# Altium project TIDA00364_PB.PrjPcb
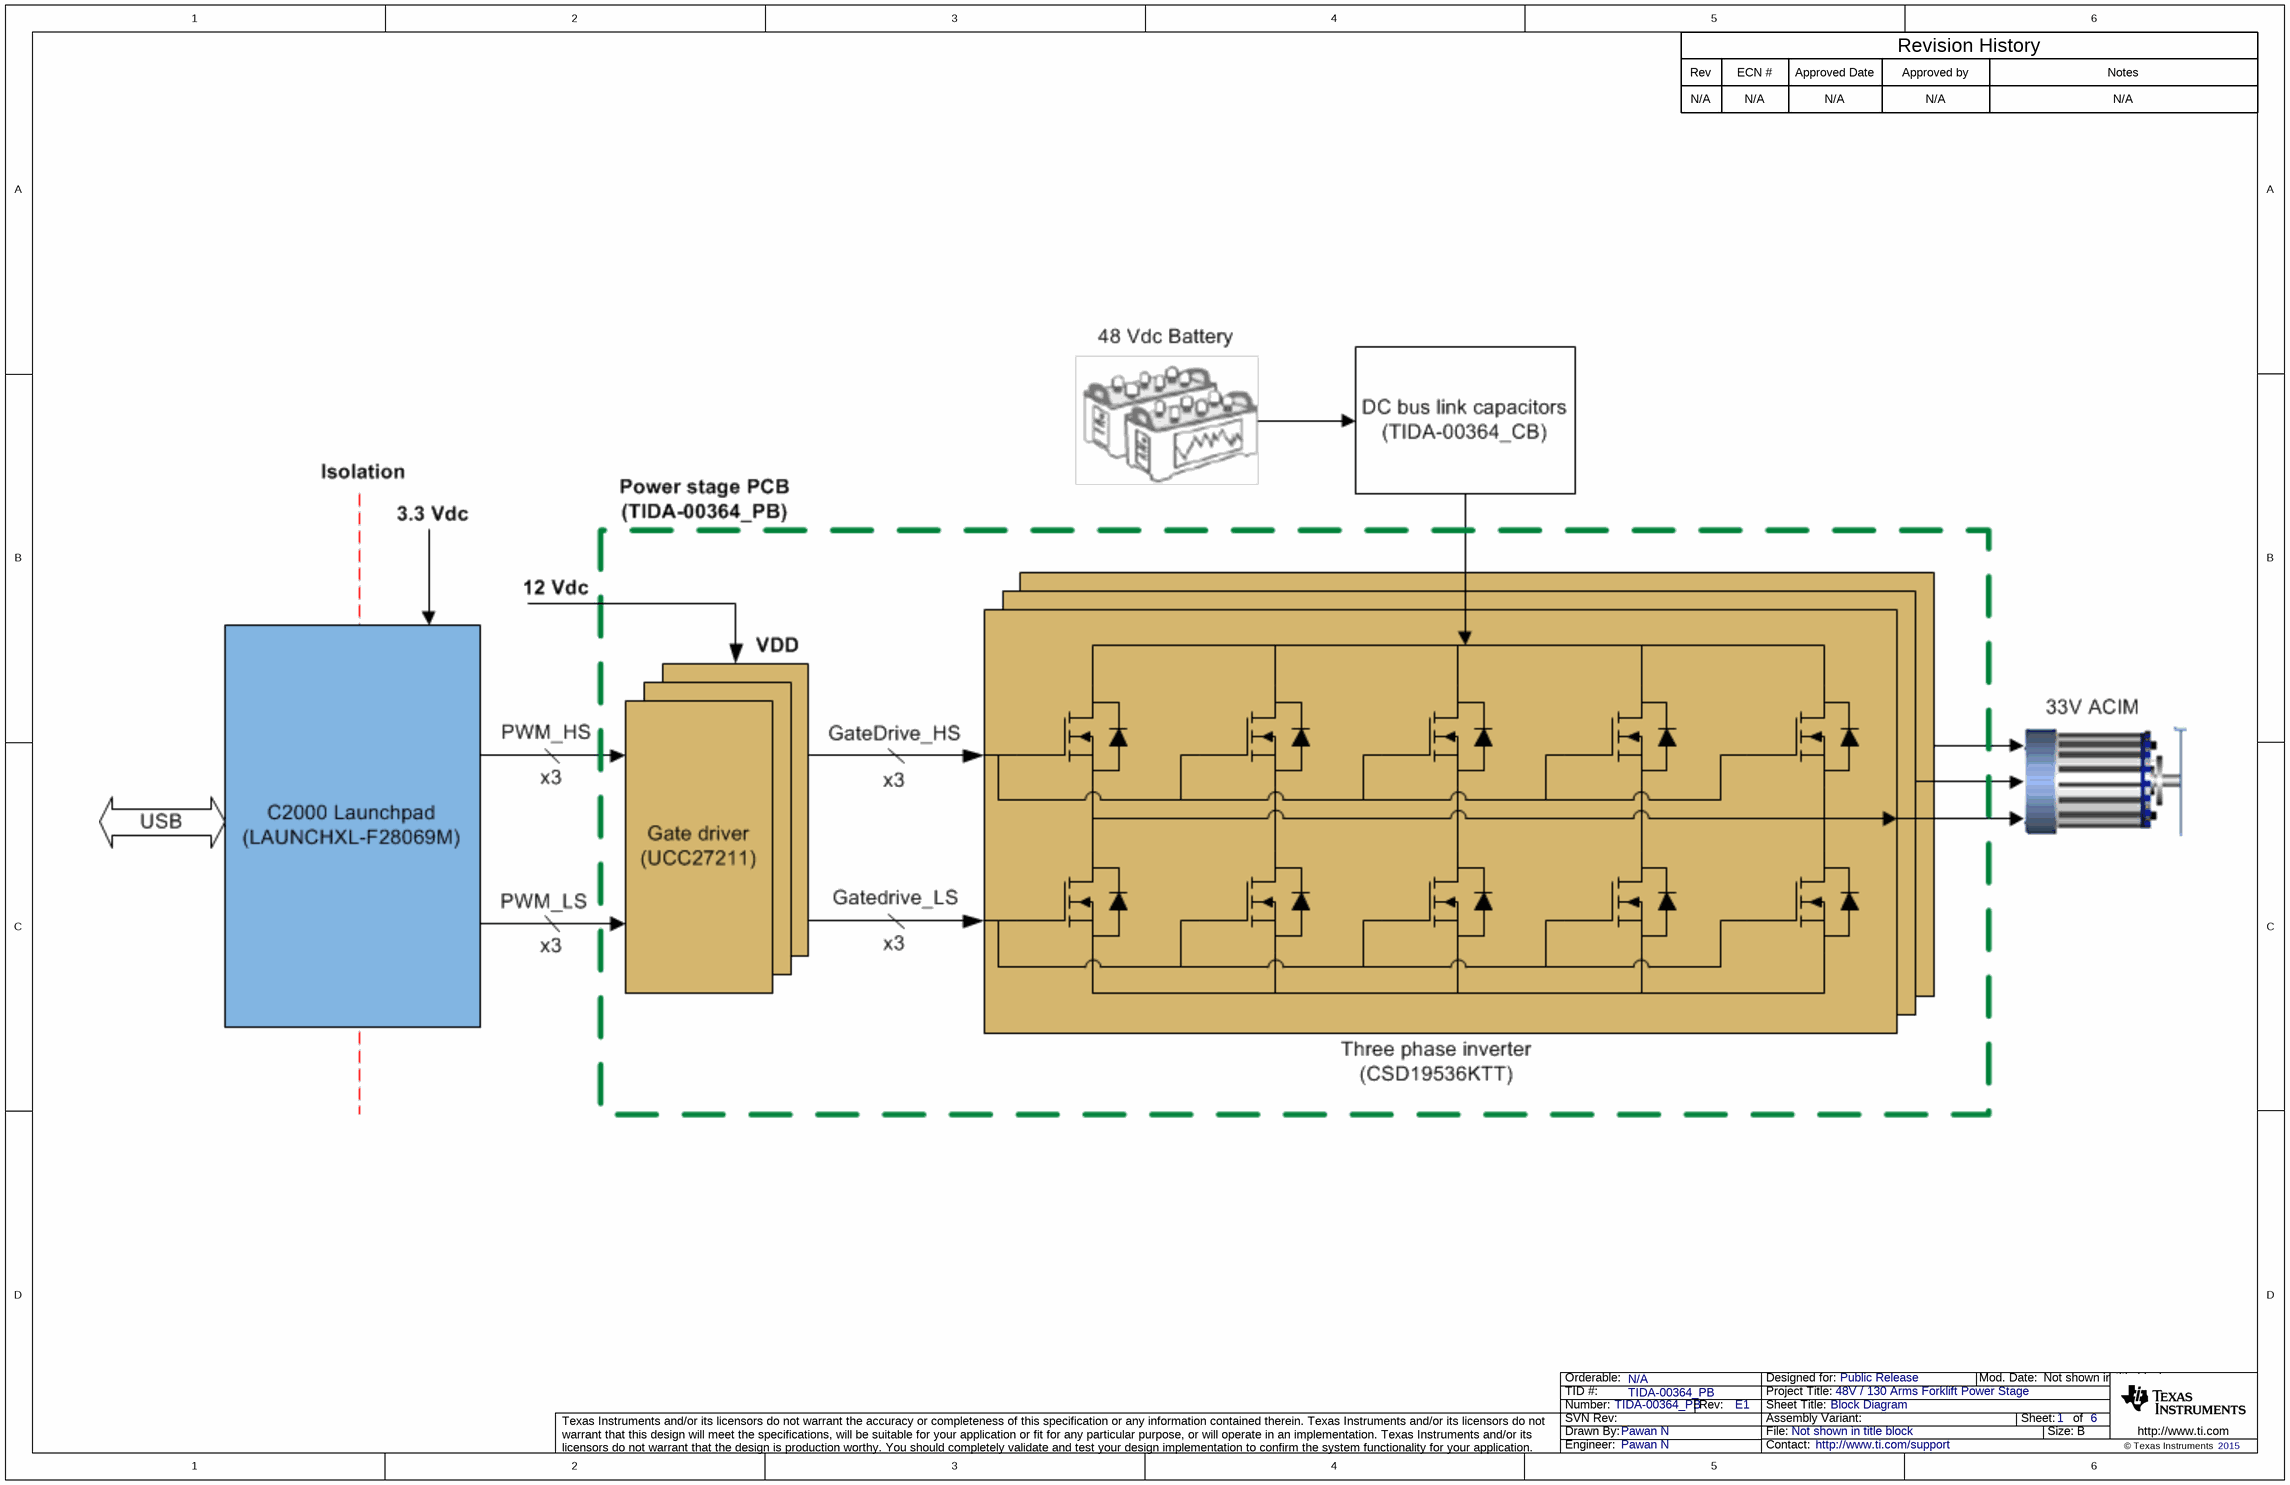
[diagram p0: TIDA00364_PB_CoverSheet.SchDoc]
CopyrightYear: 2015; EVM_Orderable: N/A; PCB_Layout: Avinash; PCB_Rev: E1; PRJ_Customer: Public Release; PRJ_Engineer: Pawan N; PRJ_Number: TIDA-00364_PB; PRJ_Title: 48V / 130 Arms Forklift Power Stage; SCH_Rev: E1; TechSupport: http://www.ti.com/support; TID: TIDA-00364_PB
6 sheets, 245 parts. Net scope: global (net labels, ports and power ports of the same name join across sheets).
Board file: TIDA00364_PB.PcbDoc
Sheets:
  TIDA00364_PB_CoverSheet.SchDoc
  TIDA00364_PB_GateDriver.SchDoc
  TIDA00364_PB_PhaseU.SchDoc
  TIDA00364_PB_PhaseV.SchDoc
  TIDA00364_PB_PhaseW.SchDoc
  TIDA00364_PB_Hardware.SchDoc

## Sheet TIDA00364_PB_CoverSheet.SchDoc: Block Diagram
size 431 x 279 mm; Date: Not shown in title block; ApprovedBy: Not shown in title block; CheckedBy: Not shown in title block; Author: Not shown in title block; CompanyName: Not shown in title block; DrawnBy: Pawan N; Engineer: Not shown in title block; Organization: Not shown in title block; Address1: Not shown in title block; Address2: Not shown in title block; Address3: Not shown in title block; Address4: Not shown in title block; DocumentNumber: 1; Revision: Use project parameter SCH_Rev; SheetNumber: 1; SheetTotal: 6; PageSetup: Record=PageOptions¦CenterHorizontal=True¦CenterVertical=True¦PrintScale=1.00¦XCorrection=1.00¦YCorrection=1.00¦PrintKind=0¦BorderSize=5000000¦LeftOffset=0¦BottomOffset=0¦Orientation=2¦PaperLength=1000¦PaperWidth=1000¦Scale=100¦PaperSource=15¦PrintQuality=600¦MediaType=1¦DitherType=10¦PaperKind=Letter¦PrintScaleMode=1

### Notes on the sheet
- Rev
- N/A
- ECN #
- Approved Date
- Approved by
- Revision History
- Notes

## Sheet TIDA00364_PB_GateDriver.SchDoc: Gate drive
size 431 x 279 mm; Date: Not shown in title block; ApprovedBy: Not shown in title block; CheckedBy: Not shown in title block; Author: Not shown in title block; CompanyName: Not shown in title block; DrawnBy: Pawan N; Engineer: Not shown in title block; Organization: Not shown in title block; Address1: Not shown in title block; Address2: Not shown in title block; Address3: Not shown in title block; Address4: Not shown in title block; DocumentNumber: 2; Revision: Use project parameter SCH_Rev; SheetNumber: 2; SheetTotal: 6; PageSetup: Record=PageOptions¦CenterHorizontal=True¦CenterVertical=True¦PrintScale=1.00¦XCorrection=1.00¦YCorrection=1.00¦PrintKind=0¦BorderSize=5000000¦LeftOffset=0¦BottomOffset=0¦Orientation=2¦PaperLength=1000¦PaperWidth=1000¦Scale=100¦PaperSource=15¦PrintQuality=600¦MediaType=1¦DitherType=10¦PaperKind=Letter¦PrintScaleMode=1
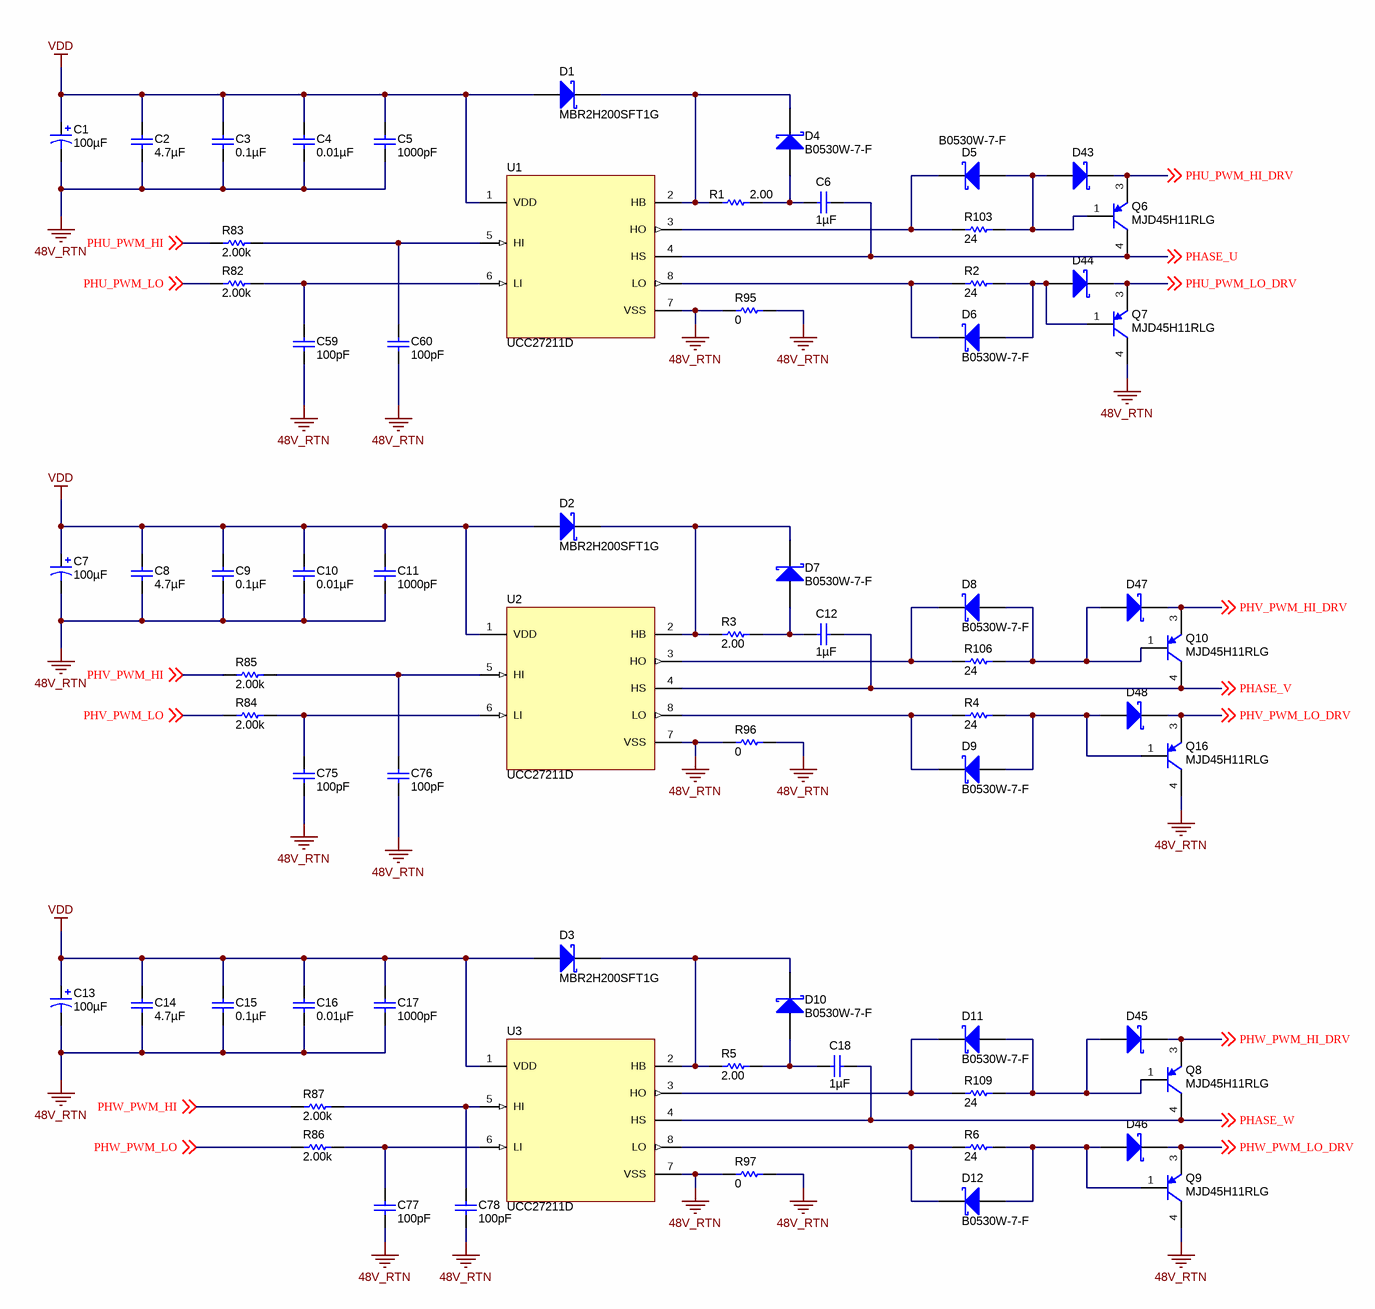
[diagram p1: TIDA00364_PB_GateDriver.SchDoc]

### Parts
C1  ValueDisplayed: 100µF  [SM_RADIAL_D8]  (hidden comment: EEE-FK1V101XP)
C2  ValueDisplayed: 4.7µF  [1206]  (hidden comment: GRM31CR71E475KA88L)
C3  ValueDisplayed: 0.1µF  [0603]  (hidden comment: C1608X7R1E104K)
C4  ValueDisplayed: 0.01µF  [0603]  (hidden comment: C1608X7R1H103K)
C5  ValueDisplayed: 1000pF  [0603]  (hidden comment: GRM188R71H102KA01D)
C6  ValueDisplayed: 1µF  [1206]  (hidden comment: C3216X7R1H105K160AB)
C7  ValueDisplayed: 100µF  [SM_RADIAL_D8]  (hidden comment: EEE-FK1V101XP)
C8  ValueDisplayed: 4.7µF  [1206]  (hidden comment: GRM31CR71E475KA88L)
C9  ValueDisplayed: 0.1µF  [0603]  (hidden comment: C1608X7R1E104K)
C10  ValueDisplayed: 0.01µF  [0603]  (hidden comment: C1608X7R1H103K)
C11  ValueDisplayed: 1000pF  [0603]  (hidden comment: GRM188R71H102KA01D)
C12  ValueDisplayed: 1µF  [1206]  (hidden comment: C3216X7R1H105K160AB)
C13  ValueDisplayed: 100µF  [SM_RADIAL_D8]  (hidden comment: EEE-FK1V101XP)
C14  ValueDisplayed: 4.7µF  [1206]  (hidden comment: GRM31CR71E475KA88L)
C15  ValueDisplayed: 0.1µF  [0603]  (hidden comment: C1608X7R1E104K)
C16  ValueDisplayed: 0.01µF  [0603]  (hidden comment: C1608X7R1H103K)
C17  ValueDisplayed: 1000pF  [0603]  (hidden comment: GRM188R71H102KA01D)
C18  ValueDisplayed: 1µF  [1206]  (hidden comment: C3216X7R1H105K160AB)
C59  ValueDisplayed: 100pF  [0402]  (hidden comment: C0402C101J3GACTU)
C60  ValueDisplayed: 100pF  [0402]  (hidden comment: C0402C101J3GACTU)
C75  ValueDisplayed: 100pF  [0402]  (hidden comment: C0402C101J3GACTU)
C76  ValueDisplayed: 100pF  [0402]  (hidden comment: C0402C101J3GACTU)
C77  ValueDisplayed: 100pF  [0402]  (hidden comment: C0402C101J3GACTU)
C78  ValueDisplayed: 100pF  [0402]  (hidden comment: C0402C101J3GACTU)
D1  MBR2H200SFT1G  [SOD-123FL]
D2  MBR2H200SFT1G  [SOD-123FL]
D3  MBR2H200SFT1G  [SOD-123FL]
D4  B0530W-7-F  [SOD-123]
D5  B0530W-7-F  [SOD-123]
D6  B0530W-7-F  [SOD-123]
D7  B0530W-7-F  [SOD-123]
D8  B0530W-7-F  [SOD-123]
D9  B0530W-7-F  [SOD-123]
D10  B0530W-7-F  [SOD-123]
D11  B0530W-7-F  [SOD-123]
D12  B0530W-7-F  [SOD-123]
D43  B0530W-7-F  [SOD-123]  (value not drawn)
D44  B0530W-7-F  [SOD-123]  (value not drawn)
D45  B0530W-7-F  [SOD-123]  (value not drawn)
D46  B0530W-7-F  [SOD-123]  (value not drawn)
D47  B0530W-7-F  [SOD-123]  (value not drawn)
D48  B0530W-7-F  [SOD-123]  (value not drawn)
Q6  MJD45H11RLG  [DPAK]
Q7  MJD45H11RLG  [DPAK]
Q8  MJD45H11RLG  [DPAK]
Q9  MJD45H11RLG  [DPAK]
Q10  MJD45H11RLG  [DPAK]
Q16  MJD45H11RLG  [DPAK]
R1  ValueDisplayed: 2.00  [1206]  (hidden comment: CRCW12062R00FKEA)
R2  ValueDisplayed: 24  [1206]  (hidden comment: CRCW120624R0JNEA)
R3  ValueDisplayed: 2.00  [1206]  (hidden comment: CRCW12062R00FKEA)
R4  ValueDisplayed: 24  [1206]  (hidden comment: CRCW120624R0JNEA)
R5  ValueDisplayed: 2.00  [1206]  (hidden comment: CRCW12062R00FKEA)
R6  ValueDisplayed: 24  [1206]  (hidden comment: CRCW120624R0JNEA)
R82  ValueDisplayed: 2.00k  [0402]  (hidden comment: CRCW04022K00FKED)
R83  ValueDisplayed: 2.00k  [0402]  (hidden comment: CRCW04022K00FKED)
R84  ValueDisplayed: 2.00k  [0402]  (hidden comment: CRCW04022K00FKED)
R85  ValueDisplayed: 2.00k  [0402]  (hidden comment: CRCW04022K00FKED)
R86  ValueDisplayed: 2.00k  [0402]  (hidden comment: CRCW04022K00FKED)
R87  ValueDisplayed: 2.00k  [0402]  (hidden comment: CRCW04022K00FKED)
R95  ValueDisplayed: 0  [1206]  (hidden comment: CRCW12060000Z0EA)
R96  ValueDisplayed: 0  [1206]  (hidden comment: CRCW12060000Z0EA)
R97  ValueDisplayed: 0  [1206]  (hidden comment: CRCW12060000Z0EA)
R103  ValueDisplayed: 24  [1206]  (hidden comment: CRCW120624R0JNEA)
R106  ValueDisplayed: 24  [1206]  (hidden comment: CRCW120624R0JNEA)
R109  ValueDisplayed: 24  [1206]  (hidden comment: CRCW120624R0JNEA)
U1  UCC27211D  [D0008A_N]
U2  UCC27211D  [D0008A_N]
U3  UCC27211D  [D0008A_N]

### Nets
48V_RTN: C1.2(-) C2.2 C3.1 C4.2 C5.2 C7.2(-) C8.2 C9.1 C10.2 C11.2 C13.2(-) C14.2 C15.1 C16.2 C17.2 C59.2 C60.2 C75.2 C76.2 C77.2 C78.2 Q7.4(C) Q9.4(C) Q16.4(C) R95.1 R95.2 R96.1 R96.2 R97.1 R97.2 U1.7(VSS) U2.7(VSS) U3.7(VSS)
VDD: C1.1(+) C2.1 C3.2 C4.1 C5.1 C7.1(+) C8.1 C9.2 C10.1 C11.1 C13.1(+) C14.1 C15.2 C16.1 C17.1 D1.2(A) D2.2(A) D3.2(A) U1.1(VDD) U2.1(VDD) U3.1(VDD)
PHASE_U: C6.2 Q6.4(C) U1.4(HS) ; off-sheet PHASE_U
PHASE_V: C12.2 Q10.4(C) U2.4(HS) ; off-sheet PHASE_V
PHASE_W: C18.2 Q8.4(C) U3.4(HS) ; off-sheet PHASE_W
PHU_PWM_HI: R83.2 ; off-sheet PHU_PWM_HI
PHU_PWM_HI_DRV: D43.1(K) Q6.3(E) ; off-sheet PHU_PWM_HI_DRV
PHU_PWM_LO: R82.2 ; off-sheet PHU_PWM_LO
PHU_PWM_LO_DRV: D44.1(K) Q7.3(E) ; off-sheet PHU_PWM_LO_DRV
PHV_PWM_HI: R85.2 ; off-sheet PHV_PWM_HI
PHV_PWM_HI_DRV: D47.1(K) Q10.3(E) ; off-sheet PHV_PWM_HI_DRV
PHV_PWM_LO: R84.2 ; off-sheet PHV_PWM_LO
PHV_PWM_LO_DRV: D48.1(K) Q16.3(E) ; off-sheet PHV_PWM_LO_DRV
PHW_PWM_HI: R87.2 ; off-sheet PHW_PWM_HI
PHW_PWM_HI_DRV: D45.1(K) Q8.3(E) ; off-sheet PHW_PWM_HI_DRV
PHW_PWM_LO: R86.2 ; off-sheet PHW_PWM_LO
PHW_PWM_LO_DRV: D46.1(K) Q9.3(E) ; off-sheet PHW_PWM_LO_DRV
NetC6_1: C6.1 D4.2(A) R1.2
NetC12_1: C12.1 D7.2(A) R3.2
NetC18_1: C18.1 D10.2(A) R5.2
NetC59_1: C59.1 R82.1 U1.6(LI)
NetC60_1: C60.1 R83.1 U1.5(HI)
NetC75_1: C75.1 R84.1 U2.6(LI)
NetC76_1: C76.1 R85.1 U2.5(HI)
NetC77_1: C77.1 R86.1 U3.6(LI)
NetC78_1: C78.1 R87.1 U3.5(HI)
NetD1_1: D1.1(K) D4.1(K) R1.1 U1.2(HB)
NetD2_1: D2.1(K) D7.1(K) R3.1 U2.2(HB)
NetD3_1: D3.1(K) D10.1(K) R5.1 U3.2(HB)
NetD5_1: D5.1(K) R103.1 U1.3(HO)
NetD5_2: D5.2(A) D43.2(A) Q6.1(B) R103.2
NetD6_1: D6.1(K) R2.1 U1.8(LO)
NetD6_2: D6.2(A) D44.2(A) Q7.1(B) R2.2
NetD8_1: D8.1(K) R106.1 U2.3(HO)
NetD8_2: D8.2(A) D47.2(A) Q10.1(B) R106.2
NetD9_1: D9.1(K) R4.1 U2.8(LO)
NetD9_2: D9.2(A) D48.2(A) Q16.1(B) R4.2
NetD11_1: D11.1(K) R109.1 U3.3(HO)
NetD11_2: D11.2(A) D45.2(A) Q8.1(B) R109.2
NetD12_1: D12.1(K) R6.1 U3.8(LO)
NetD12_2: D12.2(A) D46.2(A) Q9.1(B) R6.2

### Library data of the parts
C1 C7 C13 = EEE-FK1V101XP: CAP, AL, 100 µF, 35 V, +/- 20%, 0.34 ohm, SMD; Manufacturer: Panasonic; Polarized: Y; CompType: Capacitor; Value: 100uF; U/M: EA; Cap_F: 0.0001; Tolerance_%: 20; VDC_V: 35; Value2: 35V; ESR_ohm: 0.34; IRMS_A: 0.28; TaMin_C: -55; TaMax_C: 105; Cap_Case: D8; AEC Category: Q200
C2 C8 C14 = GRM31CR71E475KA88L: CAP, CERM, 4.7 µF, 25 V, +/- 10%, X7R, 1206; Manufacturer: MuRata; Polarized: N; CompType: Capacitor; Value: 4.7uF; U/M: EA; Cap_F: 0.0000047; Tolerance_%: 10; Value1: Unknown; VDC_V: 25; Value2: 25V; TaMin_C: -55; TaMax_C: 125; AEC Category: Q200
C3 C9 C15 = C1608X7R1E104K: CAP, CERM, 0.1 µF, 25 V, +/- 10%, X7R, 0603; Manufacturer: TDK; Polarized: N; CompType: Capacitor; Value: 0.1uF; U/M: EA; Cap_F: 0.0000001; Tolerance_%: 10; ESR_ohm: 0.017; Value1: 0.017 ohm; VDC_V: 25; Value2: 25V; TaMin_C: -55; TaMax_C: 125; AEC Category: Q200
C4 C10 C16 = C1608X7R1H103K: CAP, CERM, 0.01 µF, 50 V, +/- 10%, X7R, 0603; Manufacturer: TDK; Polarized: N; CompType: Capacitor; Value: 0.01uF; U/M: EA; Cap_F: 0.00000001; Tolerance_%: 10; ESR_ohm: 0.0539; Value1: 0.0539 ohm; VDC_V: 50; Value2: 50V; TaMin_C: -55; TaMax_C: 125; AEC Category: Q200
C5 C11 C17 = GRM188R71H102KA01D: CAP, CERM, 1000 pF, 50 V, +/- 10%, X7R, 0603; Manufacturer: MuRata; Polarized: N; CompType: Capacitor; Value: 1000pF; U/M: EA; Cap_F: 0.000000001; Tolerance_%: 10; Value1: Unknown; VDC_V: 50; Value2: 50V; TaMin_C: -55; TaMax_C: 125; AEC Category: Q200
C6 C12 C18 = C3216X7R1H105K160AB: CAP, CERM, 1 µF, 50 V, +/- 10%, X7R, 1206; Manufacturer: TDK; Polarized: N; CompType: Capacitor; Value: 1uF; U/M: EA; Cap_F: 0.000001; Tolerance_%: 10; Value1: Unknown; VDC_V: 50; Value2: 50V; TaMin_C: -55; TaMax_C: 125; AEC Category: Q200
C59 C60 C75-C78 = C0402C101J3GACTU: CAP, CERM, 100 pF, 25 V, +/- 5%, C0G/NP0, 0402; Manufacturer: Kemet; Polarized: N; CompType: Capacitor; Value: 100pF; U/M: EA; Cap_F: 0.0000000001; Tolerance_%: 5; Value1: Unknown; VDC_V: 25; Value2: 25V; TaMin_C: -55; TaMax_C: 125; AEC Category: Q200
D1-D3 = MBR2H200SFT1G: Diode, Schottky, 200 V, 2 A, SOD-123FL; Manufacturer: ON Semiconductor; U/M: EA; Vf_V: 0.94; Value: 200V; Value1: 2A; Value2: 0.94V; Io_A: 2; Vr_V: 200; TJmax_C: 150; AEC Category: Q101; AEC Qualified: N
D4-D12 D43-D48 = B0530W-7-F: Diode, Schottky, 30 V, 0.5 A, SOD-123; Manufacturer: Diodes Inc.; U/M: EA; Vf_V: 0.43; Value: 30V; Value1: 0.5A; Value2: 0.43V; Io_A: 0.5; Vr_V: 30; TJmax_C: 125; AEC Category: Q101
Q6-Q10 Q16 = MJD45H11RLG, ON Semiconductor: Transistor, PNP, 80 V, 8 A, DPAK; CompType: BJT; PNP: 1; NPN: 0; Vceo_V: 80; Value: 80 V; IcRated_A: 8; Value1: 8 A; TaMin_C: -55; TaMax_C: 150; U/M: EA; AEC Category: Q101
R1 R3 R5 = CRCW12062R00FKEA: RES, 2.00, 1%, 0.25 W, 1206; Manufacturer: Vishay-Dale; CompType: Resistor; Value: 2.00; Res_ohm: 2; Value_Code: 2R00; Tolerance_%: 1; Power_W: 0.25; Value2: 0.25W; VDC_V: 200; TempCo: 100 ppm/C; EIA_Code: E96; U/M: EA; AEC Category: Q200
R2 R4 R6 R103 R106 R109 = CRCW120624R0JNEA: RES, 24, 5%, 0.25 W, 1206; Manufacturer: Vishay-Dale; CompType: Resistor; Value: 24; Value_Code: 24R0; Tolerance_%: 5; Power_W: 0.25; Value2: 0.25W; VDC_V: 200; TempCo: 200 ppm/C; EIA_Code: E24; U/M: EA; AEC Category: Q200; SizeArea_mm2: 5.12; SizeX_mm: 3.2; SizeY_mm: 1.6; SizeZ_mm: 1.35
R82-R87 = CRCW04022K00FKED: RES, 2.00 k, 1%, 0.063 W, 0402; Manufacturer: Vishay-Dale; CompType: Resistor; Value: 2.00k; Res_ohm: 2000; Value_Code: 2k00; Tolerance_%: 1; Power_W: 0.063; Value2: 0.063W; VDC_V: 50; TempCo: 100 ppm/C; EIA_Code: E96; U/M: EA; AEC Category: Q200
R95-R97 = CRCW12060000Z0EA: RES, 0, 5%, 0.25 W, 1206; Manufacturer: Vishay-Dale; CompType: Resistor; Value: 0; Value_Code: 0000; Tolerance_%: 5; Power_W: 0.25; Value2: 0.25W; VDC_V: 200; TempCo: 200 ppm/C; SizeArea_mm2: 5.12; SizeX_mm: 3.2; SizeY_mm: 1.6; SizeZ_mm: 1.35; EIA_Code: E24; U/M: EA; AEC Category: Q200
U1-U3 = UCC27211D: 120-V Boot, 4-A Peak, High Frequency High-Side and Low-Side Driver, D0008A; Manufacturer: Texas Instruments; SymbolCreator: Altium; CompType: IC; U/M: EA

## Sheet TIDA00364_PB_PhaseU.SchDoc: Phase U Half Bridge
size 431 x 279 mm; Date: Not shown in title block; ApprovedBy: Not shown in title block; CheckedBy: Not shown in title block; Author: Not shown in title block; CompanyName: Not shown in title block; DrawnBy: Pawan N; Engineer: Not shown in title block; Organization: Not shown in title block; Address1: Not shown in title block; Address2: Not shown in title block; Address3: Not shown in title block; Address4: Not shown in title block; DocumentNumber: 3; Revision: Use project parameter SCH_Rev; SheetNumber: 3; SheetTotal: 6; PageSetup: Record=PageOptions¦CenterHorizontal=True¦CenterVertical=True¦PrintScale=1.00¦XCorrection=1.00¦YCorrection=1.00¦PrintKind=0¦BorderSize=5000000¦LeftOffset=0¦BottomOffset=0¦Orientation=2¦PaperLength=1000¦PaperWidth=1000¦Scale=100¦PaperSource=15¦PrintQuality=600¦MediaType=1¦DitherType=10¦PaperKind=Letter¦PrintScaleMode=1
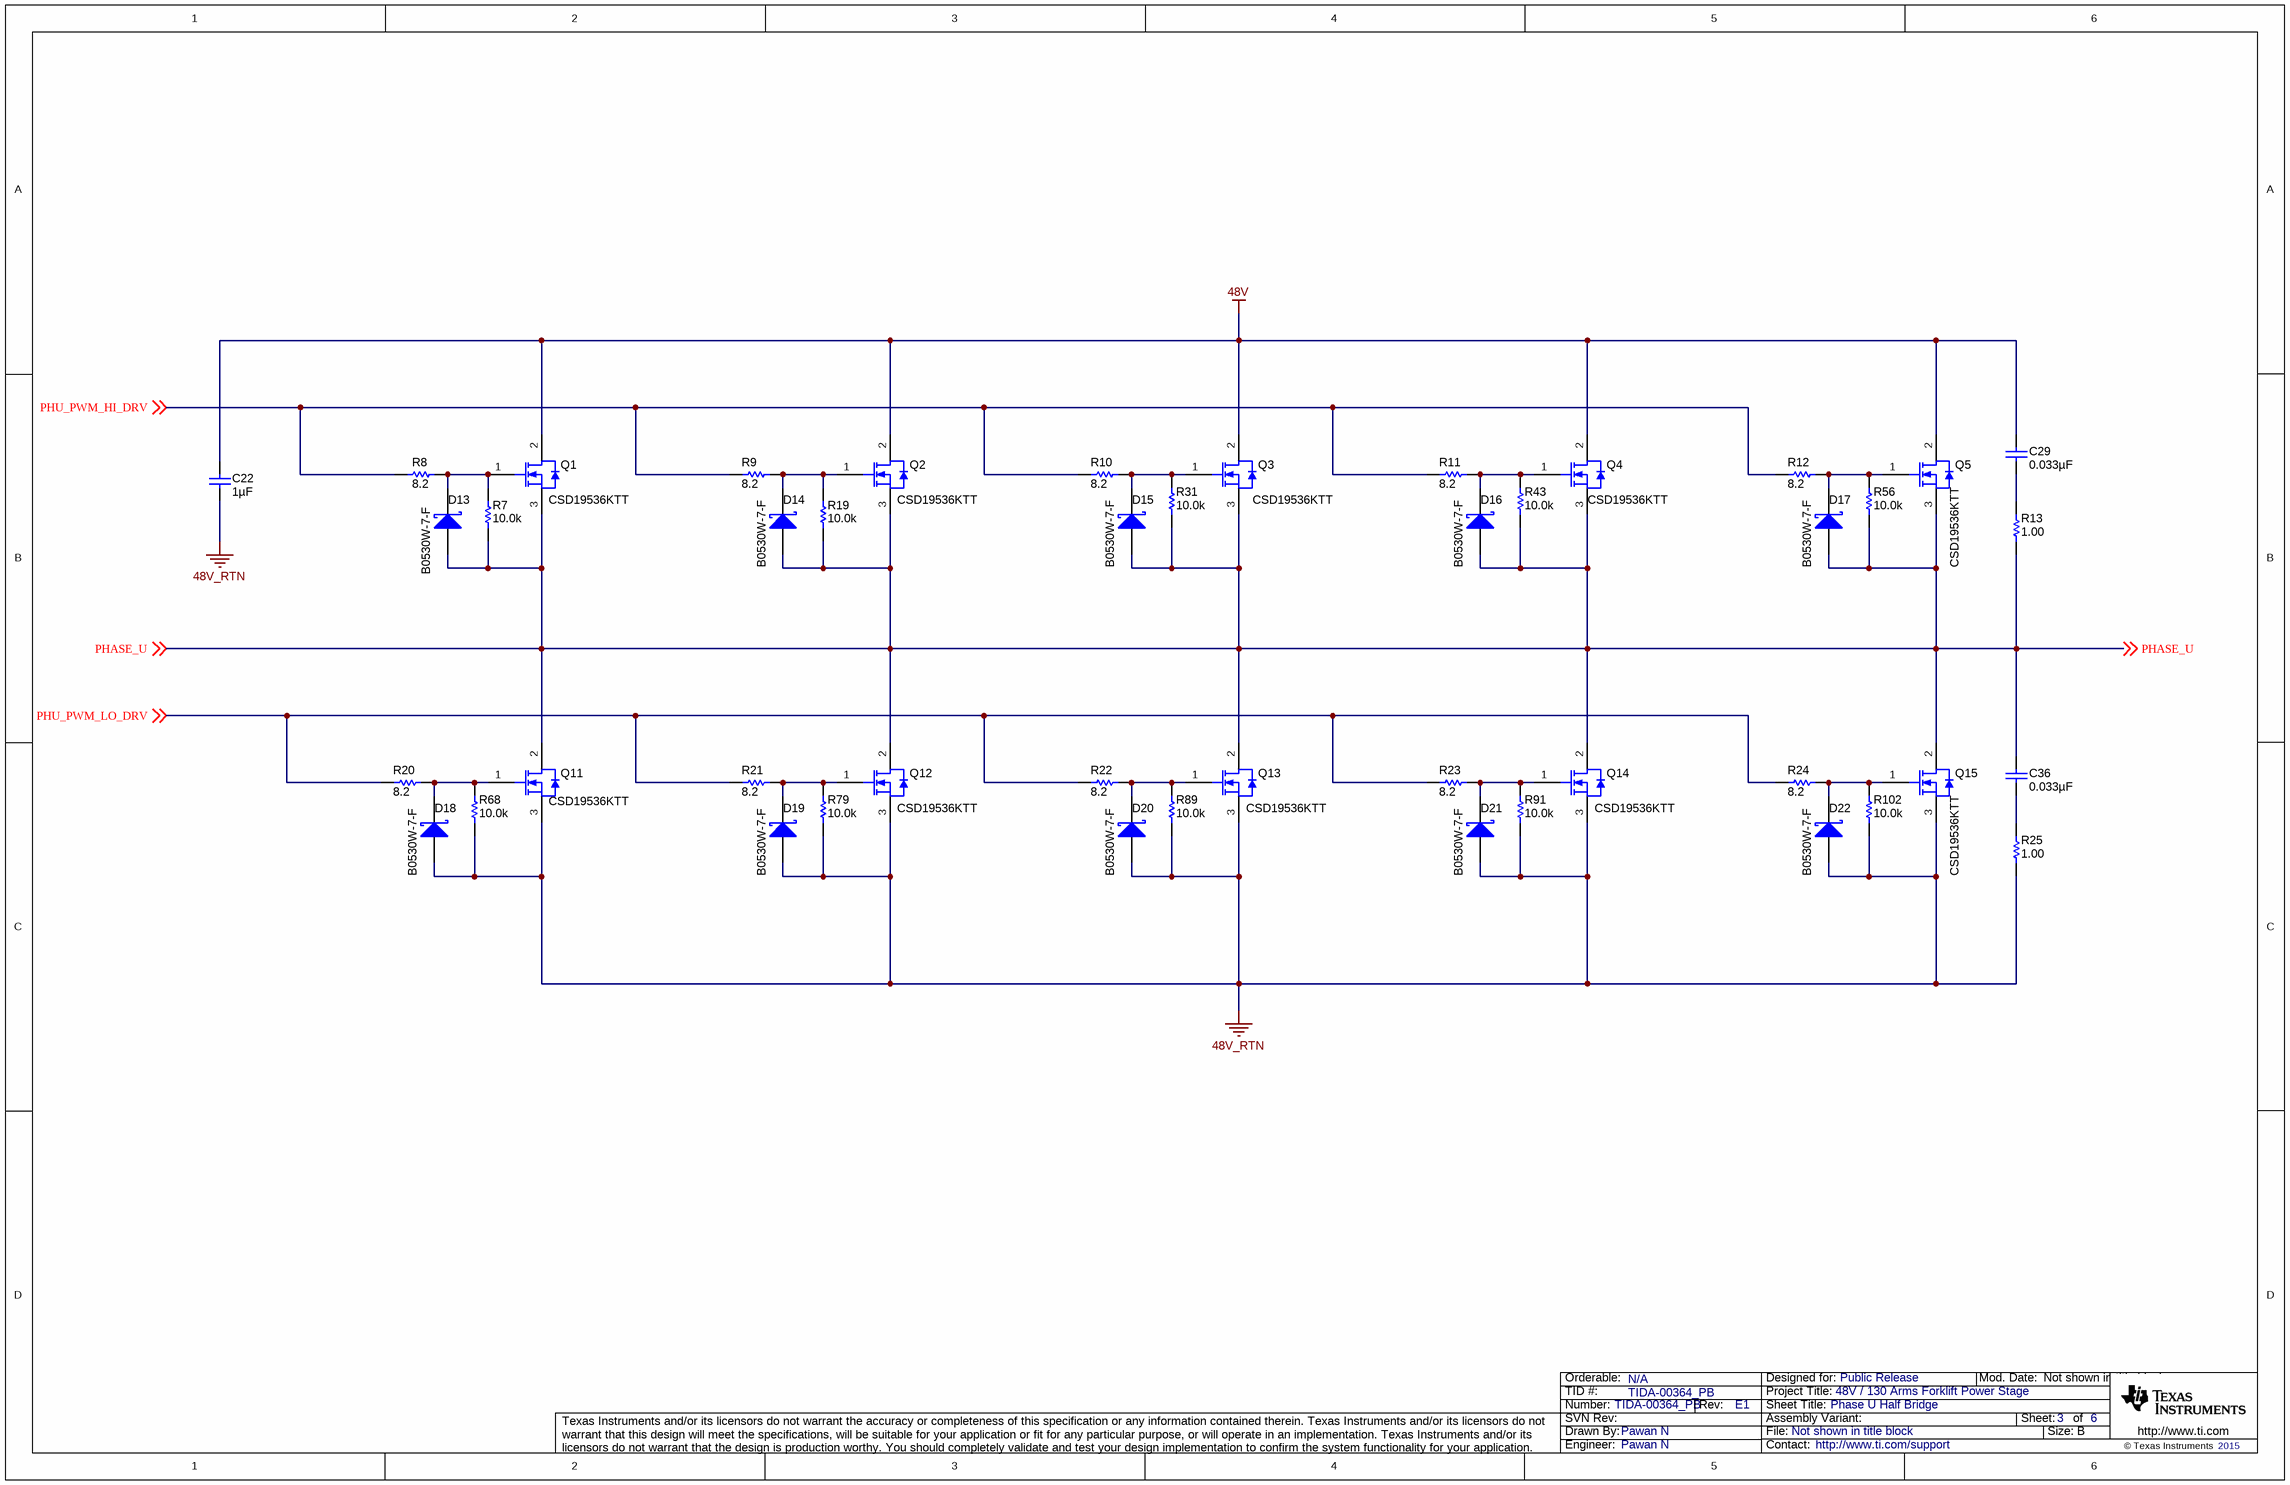
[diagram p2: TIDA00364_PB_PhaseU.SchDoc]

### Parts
C22  ValueDisplayed: 1µF  [2220_200]  (hidden comment: GRM55DR72E105KW01L)
C29  ValueDisplayed: 0.033µF  [1206]  (hidden comment: GRM31CR72E333KW03L)
C36  ValueDisplayed: 0.033µF  [1206]  (hidden comment: GRM31CR72E333KW03L)
D13  B0530W-7-F  [SOD-123]
D14  B0530W-7-F  [SOD-123]
D15  B0530W-7-F  [SOD-123]
D16  B0530W-7-F  [SOD-123]
D17  B0530W-7-F  [SOD-123]
D18  B0530W-7-F  [SOD-123]
D19  B0530W-7-F  [SOD-123]
D20  B0530W-7-F  [SOD-123]
D21  B0530W-7-F  [SOD-123]
D22  B0530W-7-F  [SOD-123]
Q1  CSD19536KTT  [KTT0002A_N]
Q2  CSD19536KTT  [KTT0002A_N]
Q3  CSD19536KTT  [KTT0002A_N]
Q4  CSD19536KTT  [KTT0002A_N]
Q5  CSD19536KTT  [KTT0002A_N]
Q11  CSD19536KTT  [KTT0002A_N]
Q12  CSD19536KTT  [KTT0002A_N]
Q13  CSD19536KTT  [KTT0002A_N]
Q14  CSD19536KTT  [KTT0002A_N]
Q15  CSD19536KTT  [KTT0002A_N]
R7  ValueDisplayed: 10.0k  [0603]  (hidden comment: CRCW060310K0FKEA)
R8  ValueDisplayed: 8.2  [0805_HV]  (hidden comment: CRCW08058R20JNEA)
R9  ValueDisplayed: 8.2  [0805_HV]  (hidden comment: CRCW08058R20JNEA)
R10  ValueDisplayed: 8.2  [0805_HV]  (hidden comment: CRCW08058R20JNEA)
R11  ValueDisplayed: 8.2  [0805_HV]  (hidden comment: CRCW08058R20JNEA)
R12  ValueDisplayed: 8.2  [0805_HV]  (hidden comment: CRCW08058R20JNEA)
R13  ValueDisplayed: 1.00  [2512]  (hidden comment: CRCW25121R00FKEG)
R19  ValueDisplayed: 10.0k  [0603]  (hidden comment: CRCW060310K0FKEA)
R20  ValueDisplayed: 8.2  [0805_HV]  (hidden comment: CRCW08058R20JNEA)
R21  ValueDisplayed: 8.2  [0805_HV]  (hidden comment: CRCW08058R20JNEA)
R22  ValueDisplayed: 8.2  [0805_HV]  (hidden comment: CRCW08058R20JNEA)
R23  ValueDisplayed: 8.2  [0805_HV]  (hidden comment: CRCW08058R20JNEA)
R24  ValueDisplayed: 8.2  [0805_HV]  (hidden comment: CRCW08058R20JNEA)
R25  ValueDisplayed: 1.00  [2512]  (hidden comment: CRCW25121R00FKEG)
R31  ValueDisplayed: 10.0k  [0603]  (hidden comment: CRCW060310K0FKEA)
R43  ValueDisplayed: 10.0k  [0603]  (hidden comment: CRCW060310K0FKEA)
R56  ValueDisplayed: 10.0k  [0603]  (hidden comment: CRCW060310K0FKEA)
R68  ValueDisplayed: 10.0k  [0603]  (hidden comment: CRCW060310K0FKEA)
R79  ValueDisplayed: 10.0k  [0603]  (hidden comment: CRCW060310K0FKEA)
R89  ValueDisplayed: 10.0k  [0603]  (hidden comment: CRCW060310K0FKEA)
R91  ValueDisplayed: 10.0k  [0603]  (hidden comment: CRCW060310K0FKEA)
R102  ValueDisplayed: 10.0k  [0603]  (hidden comment: CRCW060310K0FKEA)

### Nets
48V: C22.1 C29.1 Q1.2(D) Q2.2(D) Q3.2(D) Q4.2(D) Q5.2(D)
48V_RTN: C22.2 D18.2(A) D19.2(A) D20.2(A) D21.2(A) D22.2(A) Q11.3(S) Q12.3(S) Q13.3(S) Q14.3(S) Q15.3(S) R25.1 R68.1 R79.1 R89.1 R91.1 R102.1
PHASE_U: C36.1 D13.2(A) D14.2(A) D15.2(A) D16.2(A) D17.2(A) Q1.3(S) Q2.3(S) Q3.3(S) Q4.3(S) Q5.3(S) Q11.2(D) Q12.2(D) Q13.2(D) Q14.2(D) Q15.2(D) R7.1 R13.1 R19.1 R31.1 R43.1 R56.1 ; off-sheet PHASE_U
PHU_PWM_HI_DRV: R8.2 R9.2 R10.2 R11.2 R12.2 ; off-sheet PHU_PWM_HI_DRV
PHU_PWM_LO_DRV: R20.2 R21.2 R22.2 R23.2 R24.2 ; off-sheet PHU_PWM_LO_DRV
NetC29_2: C29.2 R13.2
NetC36_2: C36.2 R25.2
NetD13_1: D13.1(K) Q1.1(G) R7.2 R8.1
NetD14_1: D14.1(K) Q2.1(G) R9.1 R19.2
NetD15_1: D15.1(K) Q3.1(G) R10.1 R31.2
NetD16_1: D16.1(K) Q4.1(G) R11.1 R43.2
NetD17_1: D17.1(K) Q5.1(G) R12.1 R56.2
NetD18_1: D18.1(K) Q11.1(G) R20.1 R68.2
NetD19_1: D19.1(K) Q12.1(G) R21.1 R79.2
NetD20_1: D20.1(K) Q13.1(G) R22.1 R89.2
NetD21_1: D21.1(K) Q14.1(G) R23.1 R91.2
NetD22_1: D22.1(K) Q15.1(G) R24.1 R102.2

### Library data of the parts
C22 = GRM55DR72E105KW01L: CAP, CERM, 1 µF, 250 V, +/- 10%, X7R, 2220; Manufacturer: MuRata; Polarized: N; CompType: Capacitor; Value: 1uF; U/M: EA; Cap_F: 0.000001; Tolerance_%: 10; ESR_ohm: 0.007086; Value1: 0.007086 ohm; VDC_V: 250; Value2: 250V; IRMS_A: 2.0605; TaMin_C: -55; TaMax_C: 125; Cap_Case: 2220; AEC Category: Q200
C29 C36 = GRM31CR72E333KW03L: CAP, CERM, 0.033 µF, 250 V, +/- 10%, X7R, 1206; Manufacturer: MuRata; Polarized: N; CompType: Capacitor; Value: 0.033uF; U/M: EA; Cap_F: 0.000000033; Tolerance_%: 10; Value1: Unknown; VDC_V: 250; Value2: 250V; TaMin_C: -55; TaMax_C: 125; AEC Category: Q200
D13-D22 = B0530W-7-F: as D4 on sheet TIDA00364_PB_GateDriver
Q1-Q5 Q11-Q15 = CSD19536KTT: MOSFET, N-CH, 100 V, 200 A, KTT0002A; Manufacturer: Texas Instruments; Alternate Manufacturer: None; U/M: EA; ChType: N; Value: 100V; VdsMax_V: 100; Value1: ? ohm; Value2: 118 nC; QgTyp_nC: 118; Vgs_V: 20; IdsMax_A: 200; AEC Category: Q101
R7 R19 R31 R43 R56 R68 R79 R89 R91 R102 = CRCW060310K0FKEA: RES, 10.0 k, 1%, 0.1 W, 0603; Manufacturer: Vishay-Dale; CompType: Resistor; Value: 10.0k; Res_ohm: 10000; Value_Code: 10k0; Tolerance_%: 1; Power_W: 0.1; Value2: 0.1W; VDC_V: 75; TempCo: 100 ppm/C; EIA_Code: E96; U/M: EA; AEC Category: Q200
R8-R12 R20-R24 = CRCW08058R20JNEA: RES, 8.2, 5%, 0.125 W, 0805; Manufacturer: Vishay-Dale; CompType: Resistor; Value: 8.2; Value_Code: 8R20; Tolerance_%: 5; Power_W: 0.125; Value2: 0.125W; VDC_V: 150; TempCo: 200 ppm/C; EIA_Code: E24; U/M: EA; AEC Category: Q200; SizeArea_mm2: 2.5; SizeX_mm: 2; SizeY_mm: 1.25; SizeZ_mm: 1.45
R13 R25 = CRCW25121R00FKEG: RES, 1.00, 1%, 1 W, AEC-Q200 Grade 0, 2512; Manufacturer: Vishay-Dale; CompType: Resistor; Value: 1.00; Res_ohm: 1; Value_Code: 1R00; Value2: 1W; VDC_V: 500; TempCo: 100 ppm/C; EIA_Code: E96; U/M: EA; AEC Category: Q200; AEC Qualified: Y; AEC Grade: 0

## Sheet TIDA00364_PB_PhaseV.SchDoc: Phase V Half Bridge
size 431 x 279 mm; Date: Not shown in title block; ApprovedBy: Not shown in title block; CheckedBy: Not shown in title block; Author: Not shown in title block; CompanyName: Not shown in title block; DrawnBy: Pawan N; Engineer: Not shown in title block; Organization: Not shown in title block; Address1: Not shown in title block; Address2: Not shown in title block; Address3: Not shown in title block; Address4: Not shown in title block; DocumentNumber: 4; Revision: Use project parameter SCH_Rev; SheetNumber: 4; SheetTotal: 6; PageSetup: Record=PageOptions¦CenterHorizontal=True¦CenterVertical=True¦PrintScale=1.00¦XCorrection=1.00¦YCorrection=1.00¦PrintKind=0¦BorderSize=5000000¦LeftOffset=0¦BottomOffset=0¦Orientation=2¦PaperLength=1000¦PaperWidth=1000¦Scale=100¦PaperSource=15¦PrintQuality=600¦MediaType=1¦DitherType=10¦PaperKind=Letter¦PrintScaleMode=1
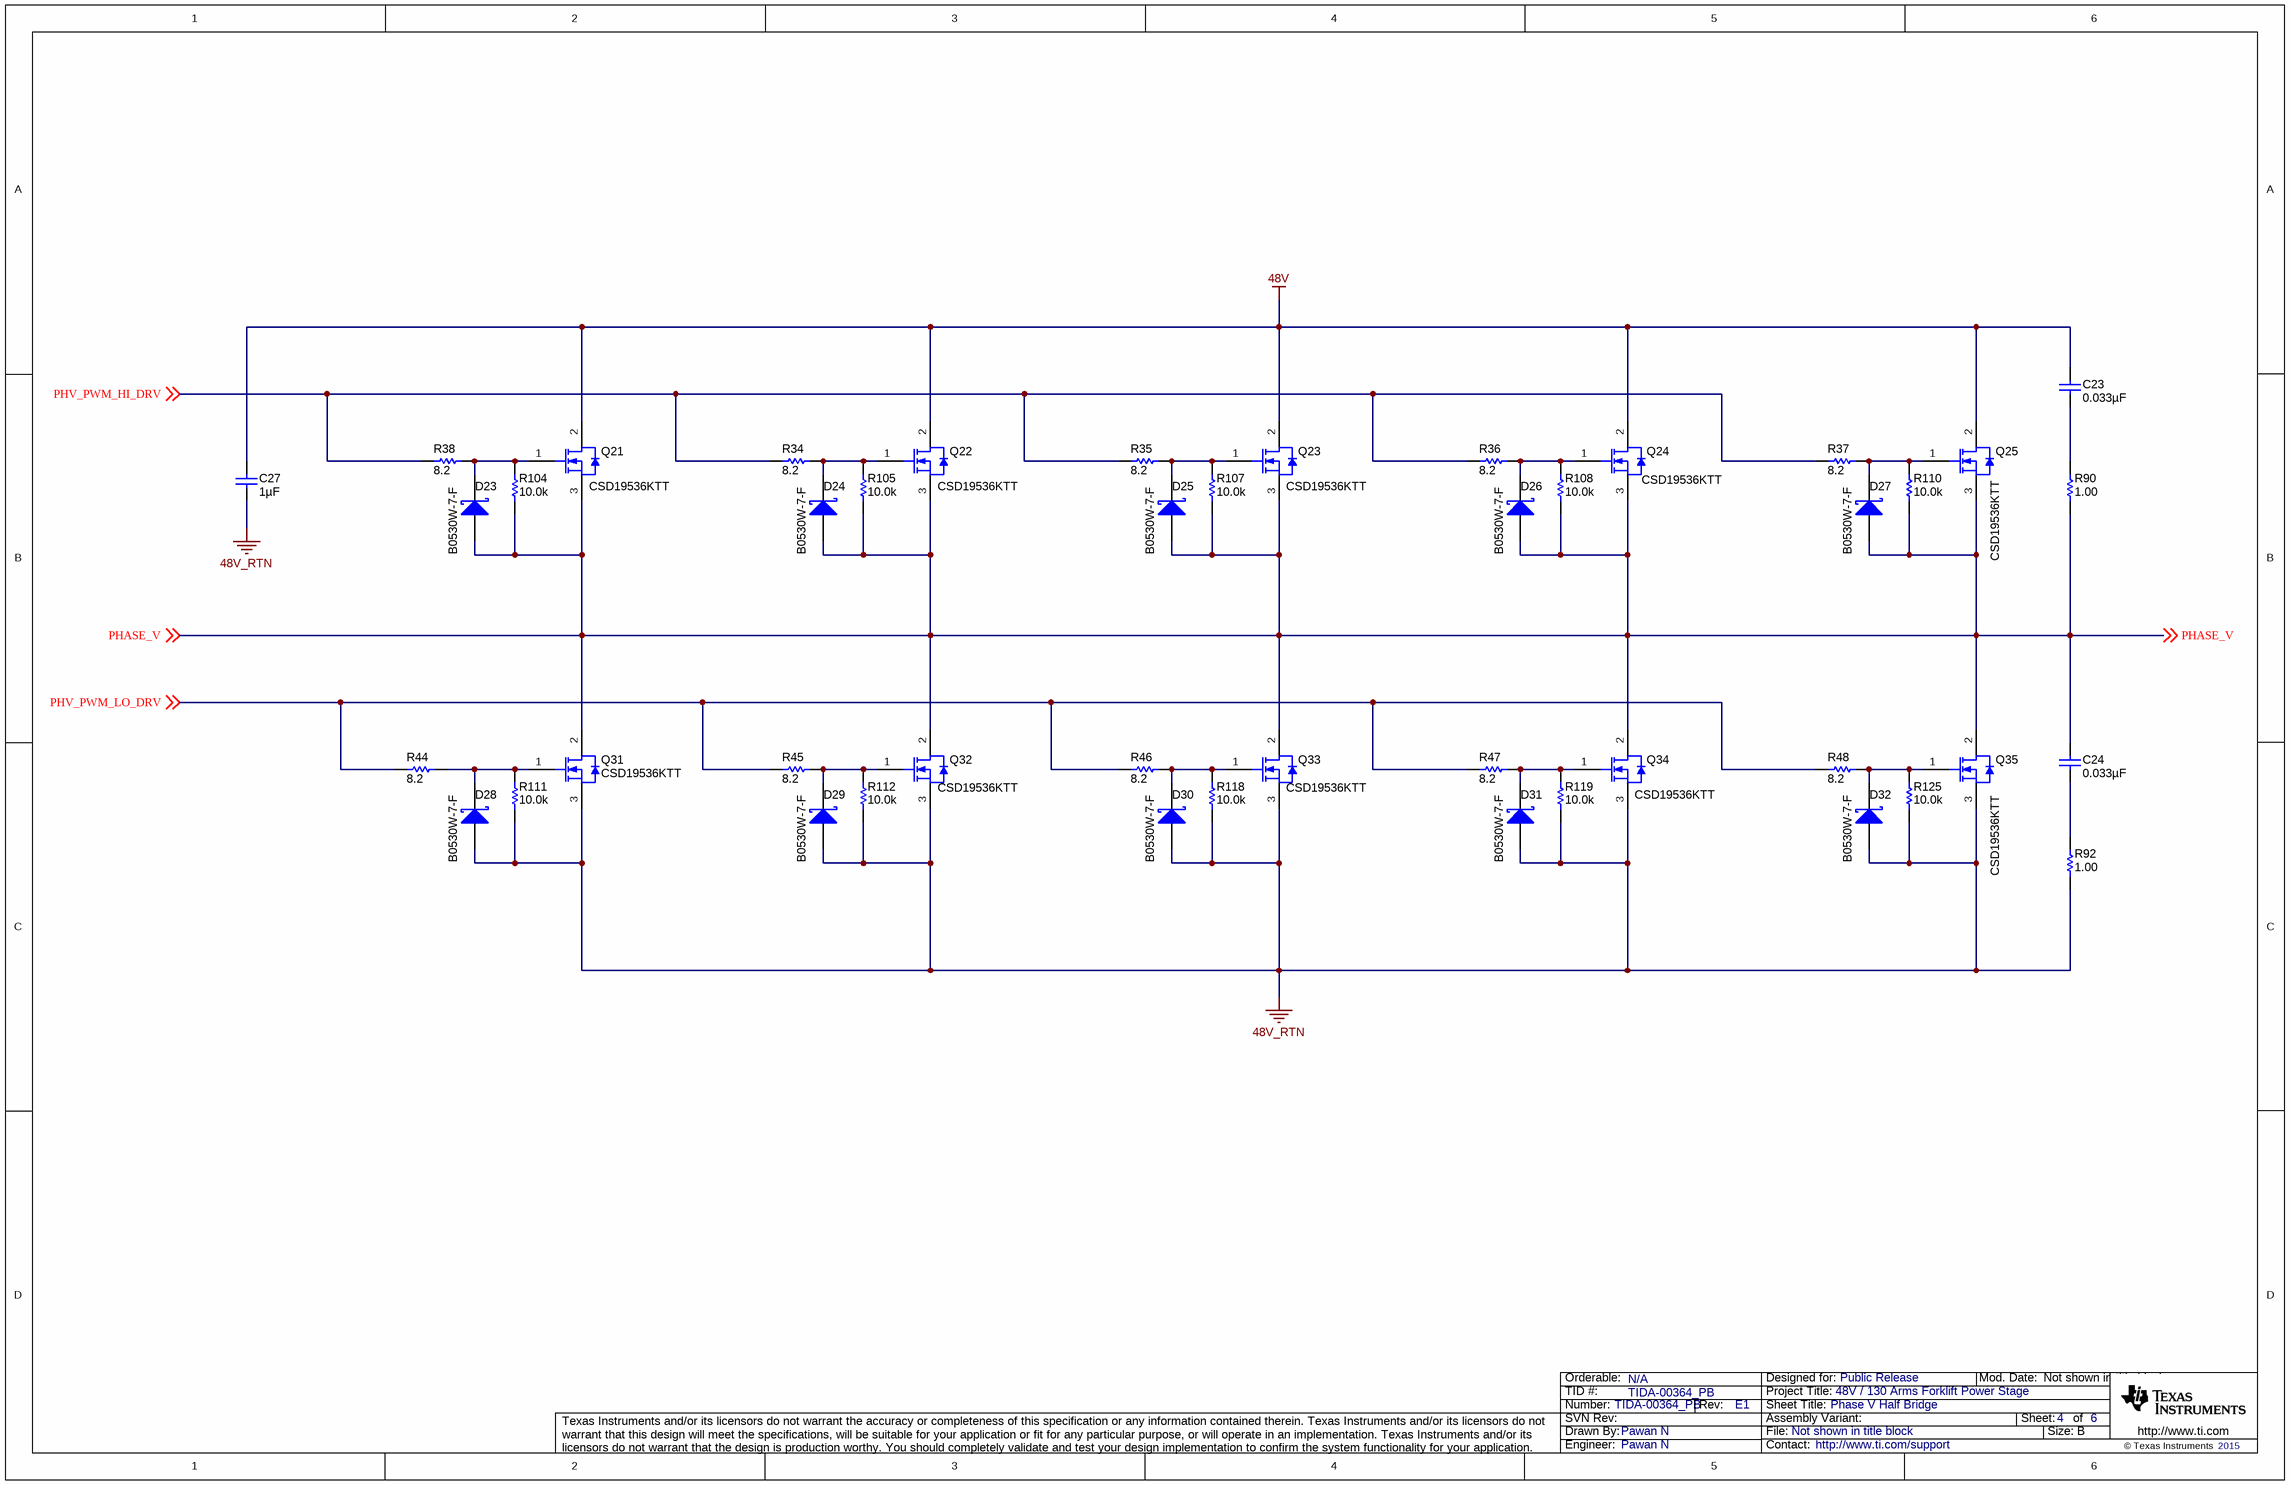
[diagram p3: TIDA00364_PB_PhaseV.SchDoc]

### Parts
C23  ValueDisplayed: 0.033µF  [1206]  (hidden comment: GRM31CR72E333KW03L)
C24  ValueDisplayed: 0.033µF  [1206]  (hidden comment: GRM31CR72E333KW03L)
C27  ValueDisplayed: 1µF  [2220_200]  (hidden comment: GRM55DR72E105KW01L)
D23  B0530W-7-F  [SOD-123]
D24  B0530W-7-F  [SOD-123]
D25  B0530W-7-F  [SOD-123]
D26  B0530W-7-F  [SOD-123]
D27  B0530W-7-F  [SOD-123]
D28  B0530W-7-F  [SOD-123]
D29  B0530W-7-F  [SOD-123]
D30  B0530W-7-F  [SOD-123]
D31  B0530W-7-F  [SOD-123]
D32  B0530W-7-F  [SOD-123]
Q21  CSD19536KTT  [KTT0002A_N]
Q22  CSD19536KTT  [KTT0002A_N]
Q23  CSD19536KTT  [KTT0002A_N]
Q24  CSD19536KTT  [KTT0002A_N]
Q25  CSD19536KTT  [KTT0002A_N]
Q31  CSD19536KTT  [KTT0002A_N]
Q32  CSD19536KTT  [KTT0002A_N]
Q33  CSD19536KTT  [KTT0002A_N]
Q34  CSD19536KTT  [KTT0002A_N]
Q35  CSD19536KTT  [KTT0002A_N]
R34  ValueDisplayed: 8.2  [0805_HV]  (hidden comment: CRCW08058R20JNEA)
R35  ValueDisplayed: 8.2  [0805_HV]  (hidden comment: CRCW08058R20JNEA)
R36  ValueDisplayed: 8.2  [0805_HV]  (hidden comment: CRCW08058R20JNEA)
R37  ValueDisplayed: 8.2  [0805_HV]  (hidden comment: CRCW08058R20JNEA)
R38  ValueDisplayed: 8.2  [0805_HV]  (hidden comment: CRCW08058R20JNEA)
R44  ValueDisplayed: 8.2  [0805_HV]  (hidden comment: CRCW08058R20JNEA)
R45  ValueDisplayed: 8.2  [0805_HV]  (hidden comment: CRCW08058R20JNEA)
R46  ValueDisplayed: 8.2  [0805_HV]  (hidden comment: CRCW08058R20JNEA)
R47  ValueDisplayed: 8.2  [0805_HV]  (hidden comment: CRCW08058R20JNEA)
R48  ValueDisplayed: 8.2  [0805_HV]  (hidden comment: CRCW08058R20JNEA)
R90  ValueDisplayed: 1.00  [2512]  (hidden comment: CRCW25121R00FKEG)
R92  ValueDisplayed: 1.00  [2512]  (hidden comment: CRCW25121R00FKEG)
R104  ValueDisplayed: 10.0k  [0603]  (hidden comment: CRCW060310K0FKEA)
R105  ValueDisplayed: 10.0k  [0603]  (hidden comment: CRCW060310K0FKEA)
R107  ValueDisplayed: 10.0k  [0603]  (hidden comment: CRCW060310K0FKEA)
R108  ValueDisplayed: 10.0k  [0603]  (hidden comment: CRCW060310K0FKEA)
R110  ValueDisplayed: 10.0k  [0603]  (hidden comment: CRCW060310K0FKEA)
R111  ValueDisplayed: 10.0k  [0603]  (hidden comment: CRCW060310K0FKEA)
R112  ValueDisplayed: 10.0k  [0603]  (hidden comment: CRCW060310K0FKEA)
R118  ValueDisplayed: 10.0k  [0603]  (hidden comment: CRCW060310K0FKEA)
R119  ValueDisplayed: 10.0k  [0603]  (hidden comment: CRCW060310K0FKEA)
R125  ValueDisplayed: 10.0k  [0603]  (hidden comment: CRCW060310K0FKEA)

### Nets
48V: C23.1 C27.1 Q21.2(D) Q22.2(D) Q23.2(D) Q24.2(D) Q25.2(D)
48V_RTN: C27.2 D28.2(A) D29.2(A) D30.2(A) D31.2(A) D32.2(A) Q31.3(S) Q32.3(S) Q33.3(S) Q34.3(S) Q35.3(S) R92.1 R111.1 R112.1 R118.1 R119.1 R125.1
PHASE_V: C24.1 D23.2(A) D24.2(A) D25.2(A) D26.2(A) D27.2(A) Q21.3(S) Q22.3(S) Q23.3(S) Q24.3(S) Q25.3(S) Q31.2(D) Q32.2(D) Q33.2(D) Q34.2(D) Q35.2(D) R90.1 R104.1 R105.1 R107.1 R108.1 R110.1 ; off-sheet PHASE_V
PHV_PWM_HI_DRV: R34.2 R35.2 R36.2 R37.2 R38.2 ; off-sheet PHV_PWM_HI_DRV
PHV_PWM_LO_DRV: R44.2 R45.2 R46.2 R47.2 R48.2 ; off-sheet PHV_PWM_LO_DRV
NetC23_2: C23.2 R90.2
NetC24_2: C24.2 R92.2
NetD23_1: D23.1(K) Q21.1(G) R38.1 R104.2
NetD24_1: D24.1(K) Q22.1(G) R34.1 R105.2
NetD25_1: D25.1(K) Q23.1(G) R35.1 R107.2
NetD26_1: D26.1(K) Q24.1(G) R36.1 R108.2
NetD27_1: D27.1(K) Q25.1(G) R37.1 R110.2
NetD28_1: D28.1(K) Q31.1(G) R44.1 R111.2
NetD29_1: D29.1(K) Q32.1(G) R45.1 R112.2
NetD30_1: D30.1(K) Q33.1(G) R46.1 R118.2
NetD31_1: D31.1(K) Q34.1(G) R47.1 R119.2
NetD32_1: D32.1(K) Q35.1(G) R48.1 R125.2

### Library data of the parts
C23 C24 = GRM31CR72E333KW03L: as C29 on sheet TIDA00364_PB_PhaseU
C27 = GRM55DR72E105KW01L: as C22 on sheet TIDA00364_PB_PhaseU
D23-D32 = B0530W-7-F: as D4 on sheet TIDA00364_PB_GateDriver
Q21-Q25 Q31-Q35 = CSD19536KTT: as Q1 on sheet TIDA00364_PB_PhaseU
R34-R38 R44-R48 = CRCW08058R20JNEA: as R8 on sheet TIDA00364_PB_PhaseU
R90 R92 = CRCW25121R00FKEG: as R13 on sheet TIDA00364_PB_PhaseU
R104 R105 R107 R108 R110-R112 R118 R119 R125 = CRCW060310K0FKEA: as R7 on sheet TIDA00364_PB_PhaseU

## Sheet TIDA00364_PB_PhaseW.SchDoc: Phase W Half Bridge
size 431 x 279 mm; Date: Not shown in title block; ApprovedBy: Not shown in title block; CheckedBy: Not shown in title block; Author: Not shown in title block; CompanyName: Not shown in title block; DrawnBy: Pawan N; Engineer: Not shown in title block; Organization: Not shown in title block; Address1: Not shown in title block; Address2: Not shown in title block; Address3: Not shown in title block; Address4: Not shown in title block; DocumentNumber: 5; Revision: Use project parameter SCH_Rev; SheetNumber: 5; SheetTotal: 6; PageSetup: Record=PageOptions¦CenterHorizontal=True¦CenterVertical=True¦PrintScale=1.00¦XCorrection=1.00¦YCorrection=1.00¦PrintKind=0¦BorderSize=5000000¦LeftOffset=0¦BottomOffset=0¦Orientation=2¦PaperLength=1000¦PaperWidth=1000¦Scale=100¦PaperSource=15¦PrintQuality=600¦MediaType=1¦DitherType=10¦PaperKind=Letter¦PrintScaleMode=1
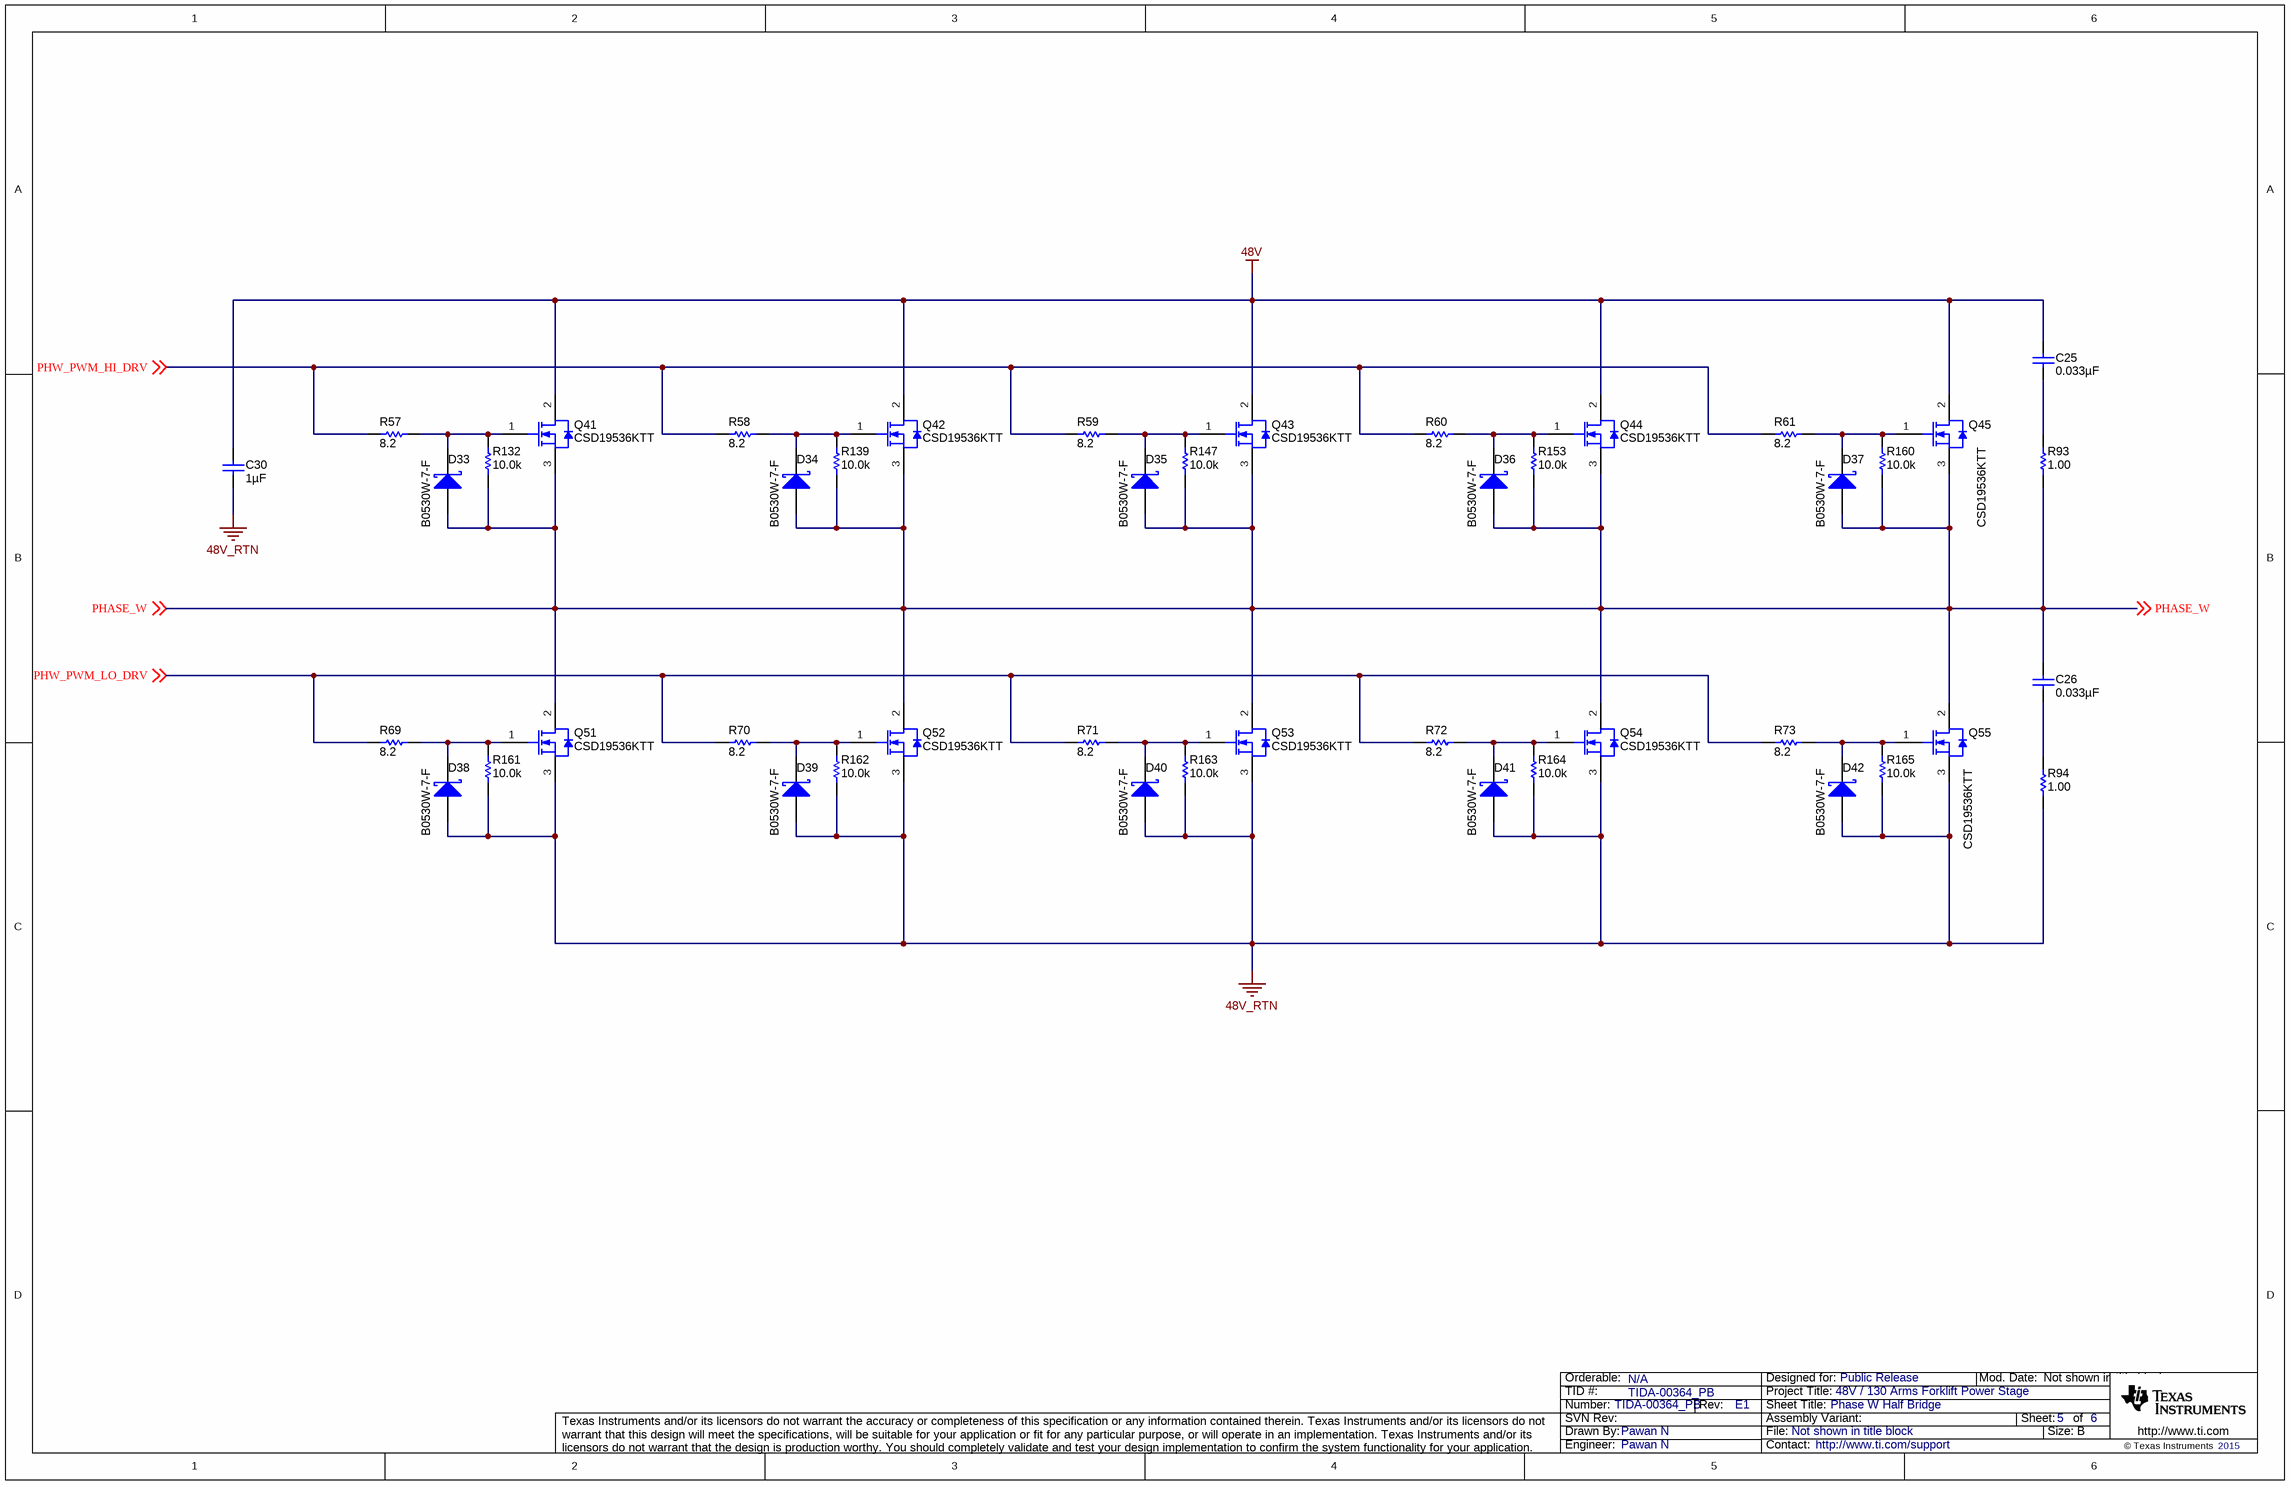
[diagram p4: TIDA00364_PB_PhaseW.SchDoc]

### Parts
C25  ValueDisplayed: 0.033µF  [1206]  (hidden comment: GRM31CR72E333KW03L)
C26  ValueDisplayed: 0.033µF  [1206]  (hidden comment: GRM31CR72E333KW03L)
C30  ValueDisplayed: 1µF  [2220_200]  (hidden comment: GRM55DR72E105KW01L)
D33  B0530W-7-F  [SOD-123]
D34  B0530W-7-F  [SOD-123]
D35  B0530W-7-F  [SOD-123]
D36  B0530W-7-F  [SOD-123]
D37  B0530W-7-F  [SOD-123]
D38  B0530W-7-F  [SOD-123]
D39  B0530W-7-F  [SOD-123]
D40  B0530W-7-F  [SOD-123]
D41  B0530W-7-F  [SOD-123]
D42  B0530W-7-F  [SOD-123]
Q41  CSD19536KTT  [KTT0002A_N]
Q42  CSD19536KTT  [KTT0002A_N]
Q43  CSD19536KTT  [KTT0002A_N]
Q44  CSD19536KTT  [KTT0002A_N]
Q45  CSD19536KTT  [KTT0002A_N]
Q51  CSD19536KTT  [KTT0002A_N]
Q52  CSD19536KTT  [KTT0002A_N]
Q53  CSD19536KTT  [KTT0002A_N]
Q54  CSD19536KTT  [KTT0002A_N]
Q55  CSD19536KTT  [KTT0002A_N]
R57  ValueDisplayed: 8.2  [0805_HV]  (hidden comment: CRCW08058R20JNEA)
R58  ValueDisplayed: 8.2  [0805_HV]  (hidden comment: CRCW08058R20JNEA)
R59  ValueDisplayed: 8.2  [0805_HV]  (hidden comment: CRCW08058R20JNEA)
R60  ValueDisplayed: 8.2  [0805_HV]  (hidden comment: CRCW08058R20JNEA)
R61  ValueDisplayed: 8.2  [0805_HV]  (hidden comment: CRCW08058R20JNEA)
R69  ValueDisplayed: 8.2  [0805_HV]  (hidden comment: CRCW08058R20JNEA)
R70  ValueDisplayed: 8.2  [0805_HV]  (hidden comment: CRCW08058R20JNEA)
R71  ValueDisplayed: 8.2  [0805_HV]  (hidden comment: CRCW08058R20JNEA)
R72  ValueDisplayed: 8.2  [0805_HV]  (hidden comment: CRCW08058R20JNEA)
R73  ValueDisplayed: 8.2  [0805_HV]  (hidden comment: CRCW08058R20JNEA)
R93  ValueDisplayed: 1.00  [2512]  (hidden comment: CRCW25121R00FKEG)
R94  ValueDisplayed: 1.00  [2512]  (hidden comment: CRCW25121R00FKEG)
R132  ValueDisplayed: 10.0k  [0603]  (hidden comment: CRCW060310K0FKEA)
R139  ValueDisplayed: 10.0k  [0603]  (hidden comment: CRCW060310K0FKEA)
R147  ValueDisplayed: 10.0k  [0603]  (hidden comment: CRCW060310K0FKEA)
R153  ValueDisplayed: 10.0k  [0603]  (hidden comment: CRCW060310K0FKEA)
R160  ValueDisplayed: 10.0k  [0603]  (hidden comment: CRCW060310K0FKEA)
R161  ValueDisplayed: 10.0k  [0603]  (hidden comment: CRCW060310K0FKEA)
R162  ValueDisplayed: 10.0k  [0603]  (hidden comment: CRCW060310K0FKEA)
R163  ValueDisplayed: 10.0k  [0603]  (hidden comment: CRCW060310K0FKEA)
R164  ValueDisplayed: 10.0k  [0603]  (hidden comment: CRCW060310K0FKEA)
R165  ValueDisplayed: 10.0k  [0603]  (hidden comment: CRCW060310K0FKEA)

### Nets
48V: C25.1 C30.1 Q41.2(D) Q42.2(D) Q43.2(D) Q44.2(D) Q45.2(D)
48V_RTN: C30.2 D38.2(A) D39.2(A) D40.2(A) D41.2(A) D42.2(A) Q51.3(S) Q52.3(S) Q53.3(S) Q54.3(S) Q55.3(S) R94.1 R161.1 R162.1 R163.1 R164.1 R165.1
PHASE_W: C26.1 D33.2(A) D34.2(A) D35.2(A) D36.2(A) D37.2(A) Q41.3(S) Q42.3(S) Q43.3(S) Q44.3(S) Q45.3(S) Q51.2(D) Q52.2(D) Q53.2(D) Q54.2(D) Q55.2(D) R93.1 R132.1 R139.1 R147.1 R153.1 R160.1 ; off-sheet PHASE_W
PHW_PWM_HI_DRV: R57.2 R58.2 R59.2 R60.2 R61.2 ; off-sheet PHW_PWM_HI_DRV
PHW_PWM_LO_DRV: R69.2 R70.2 R71.2 R72.2 R73.2 ; off-sheet PHW_PWM_LO_DRV
NetC25_2: C25.2 R93.2
NetC26_2: C26.2 R94.2
NetD33_1: D33.1(K) Q41.1(G) R57.1 R132.2
NetD34_1: D34.1(K) Q42.1(G) R58.1 R139.2
NetD35_1: D35.1(K) Q43.1(G) R59.1 R147.2
NetD36_1: D36.1(K) Q44.1(G) R60.1 R153.2
NetD37_1: D37.1(K) Q45.1(G) R61.1 R160.2
NetD38_1: D38.1(K) Q51.1(G) R69.1 R161.2
NetD39_1: D39.1(K) Q52.1(G) R70.1 R162.2
NetD40_1: D40.1(K) Q53.1(G) R71.1 R163.2
NetD41_1: D41.1(K) Q54.1(G) R72.1 R164.2
NetD42_1: D42.1(K) Q55.1(G) R73.1 R165.2

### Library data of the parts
C25 C26 = GRM31CR72E333KW03L: as C29 on sheet TIDA00364_PB_PhaseU
C30 = GRM55DR72E105KW01L: as C22 on sheet TIDA00364_PB_PhaseU
D33-D42 = B0530W-7-F: as D4 on sheet TIDA00364_PB_GateDriver
Q41-Q45 Q51-Q55 = CSD19536KTT: as Q1 on sheet TIDA00364_PB_PhaseU
R57-R61 R69-R73 = CRCW08058R20JNEA: as R8 on sheet TIDA00364_PB_PhaseU
R93 R94 = CRCW25121R00FKEG: as R13 on sheet TIDA00364_PB_PhaseU
R132 R139 R147 R153 R160-R165 = CRCW060310K0FKEA: as R7 on sheet TIDA00364_PB_PhaseU

## Sheet TIDA00364_PB_Hardware.SchDoc: Connector and Hardware
size 431 x 279 mm; Date: Not shown in title block; ApprovedBy: Not shown in title block; CheckedBy: Not shown in title block; Author: Not shown in title block; CompanyName: Not shown in title block; DrawnBy: Pawan N; Engineer: Not shown in title block; Organization: Not shown in title block; Address1: Not shown in title block; Address2: Not shown in title block; Address3: Not shown in title block; Address4: Not shown in title block; DocumentNumber: 7; Revision: Use project parameter SCH_Rev; SheetNumber: 6; SheetTotal: 6; PageSetup: Record=PageOptions¦CenterHorizontal=True¦CenterVertical=True¦PrintScale=1.00¦XCorrection=1.00¦YCorrection=1.00¦PrintKind=0¦BorderSize=5000000¦LeftOffset=0¦BottomOffset=0¦Orientation=2¦PaperLength=1000¦PaperWidth=1000¦Scale=100¦PaperSource=15¦PrintQuality=600¦MediaType=1¦DitherType=10¦PaperKind=Letter¦PrintScaleMode=1
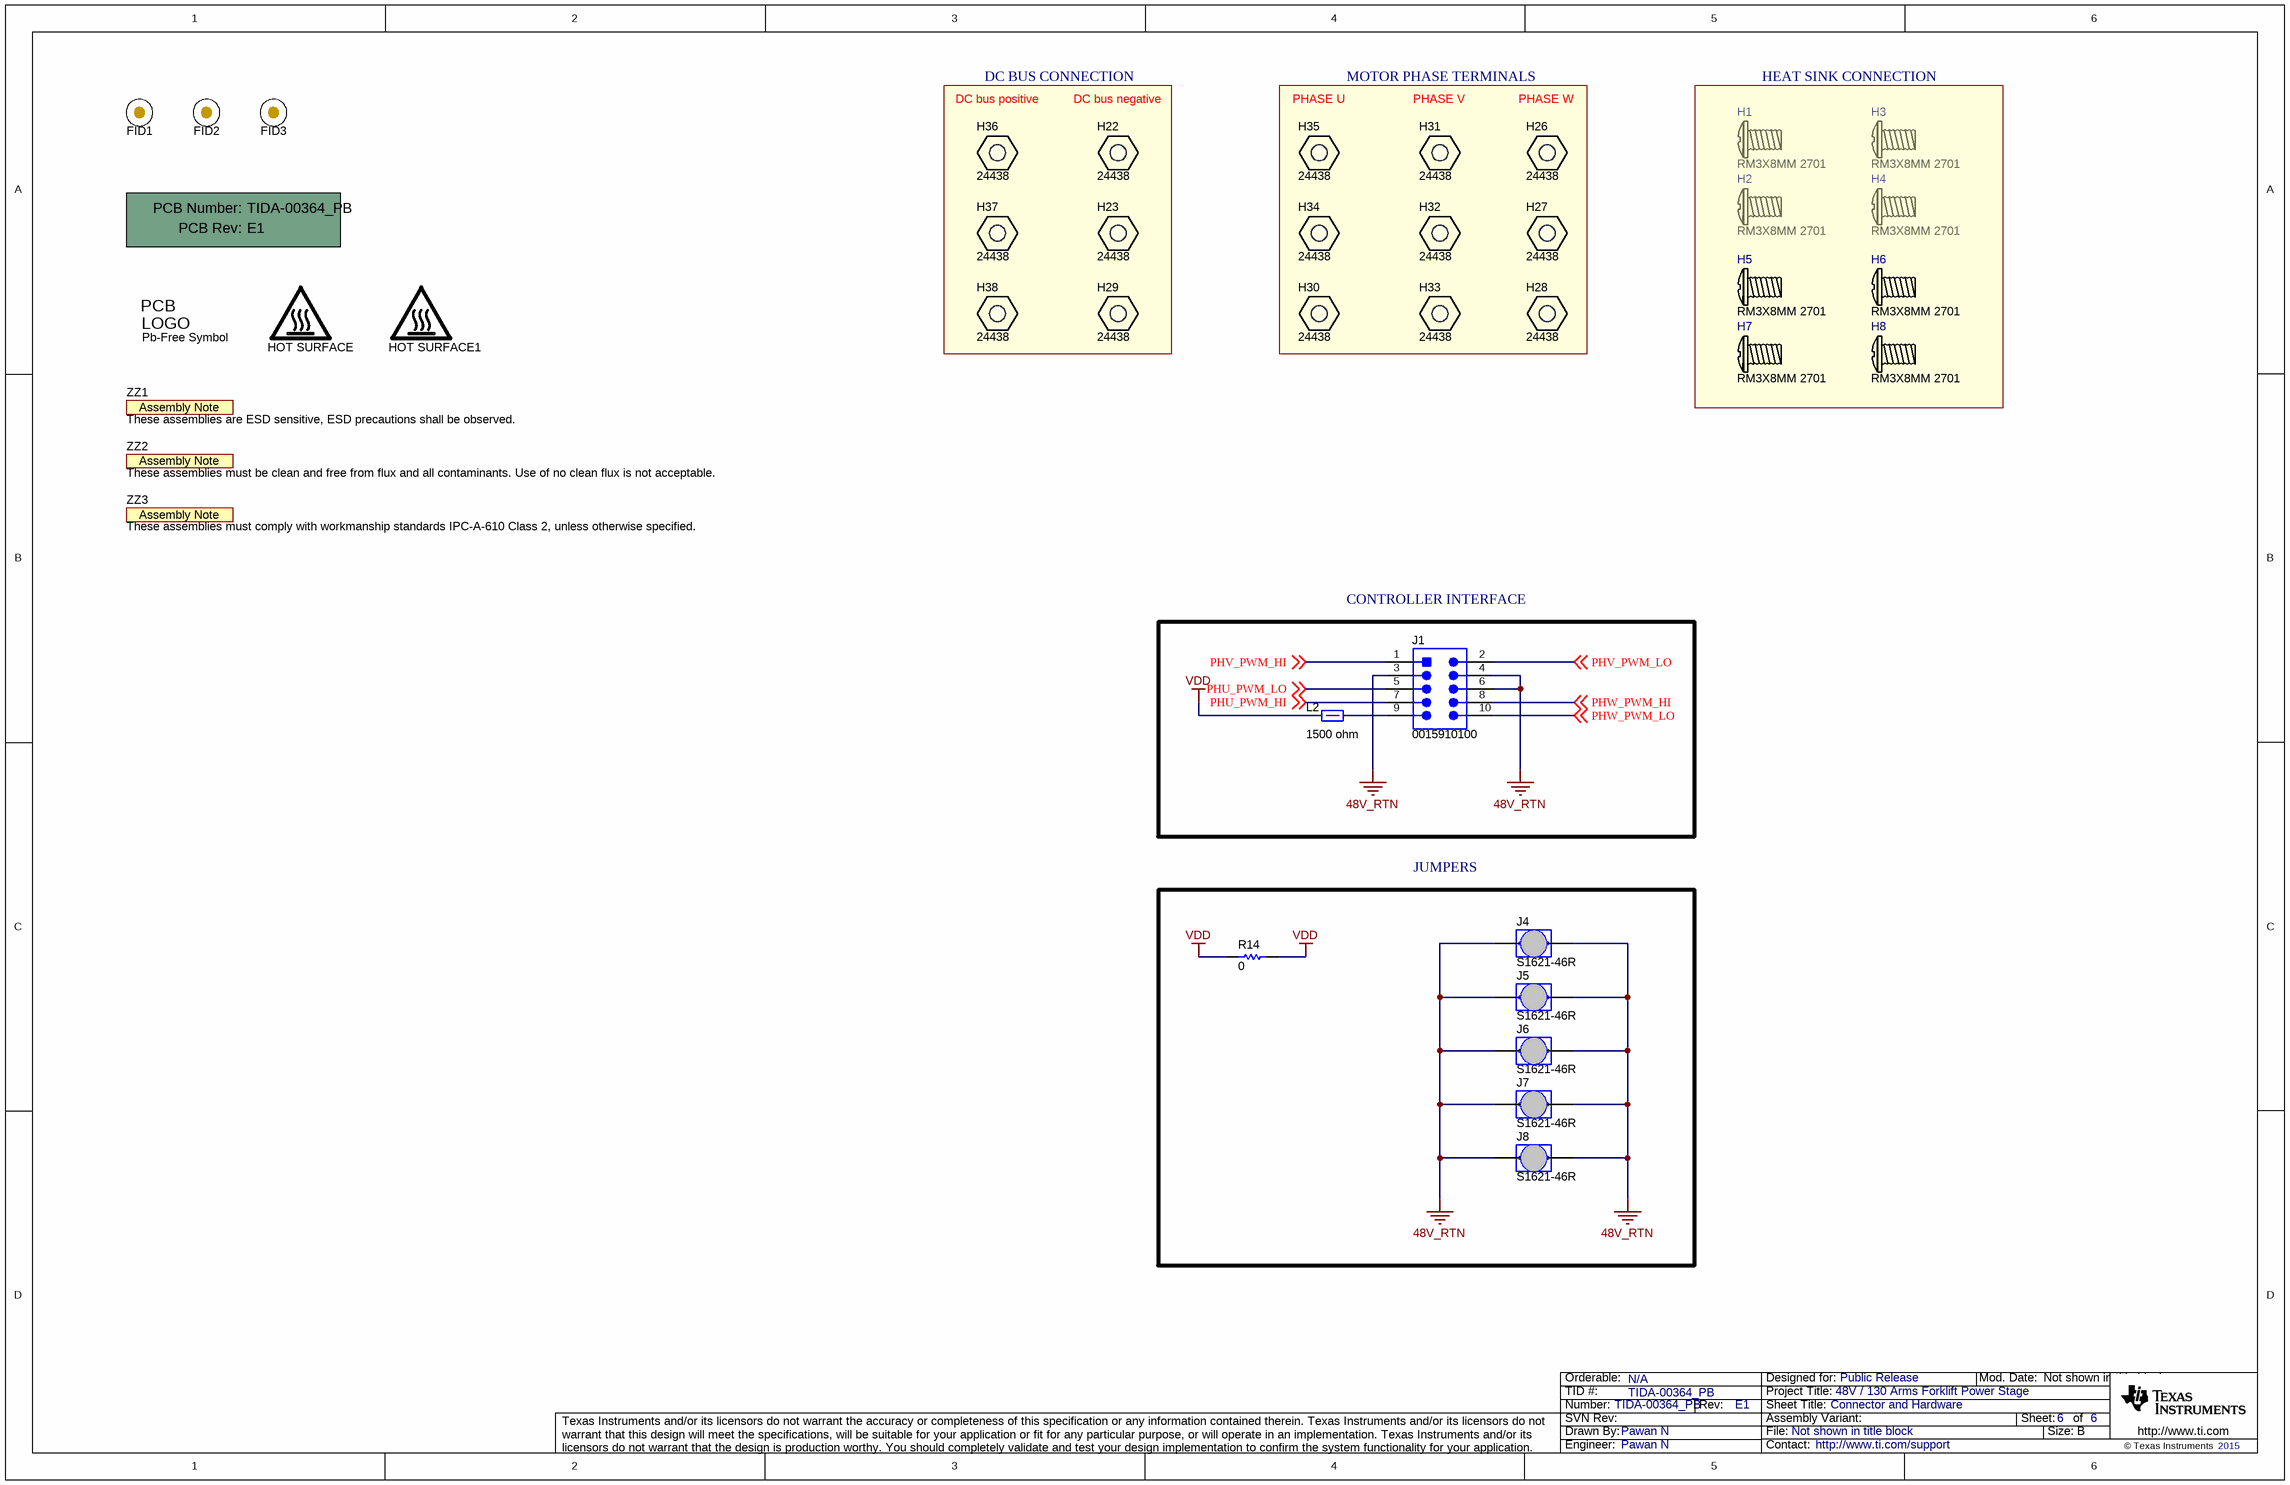
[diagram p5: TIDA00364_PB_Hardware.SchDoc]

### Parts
!PCB1  Printed Circuit Board  (value not drawn)  (mechanical)
FID1  Fiducial  [Fiducial10-20]  (value not drawn)
FID2  Fiducial  [Fiducial10-20]  (value not drawn)
FID3  Fiducial  [Fiducial10-20]  (value not drawn)
H1  RM3X8MM 2701  [APM_RM3X8MM 2701]
H2  RM3X8MM 2701  [APM_RM3X8MM 2701]
H3  RM3X8MM 2701  [APM_RM3X8MM 2701]
H4  RM3X8MM 2701  [APM_RM3X8MM 2701]
H5  RM3X8MM 2701  [APM_RM3X8MM 2701]
H6  RM3X8MM 2701  [APM_RM3X8MM 2701]
H7  RM3X8MM 2701  [APM_RM3X8MM 2701]
H8  RM3X8MM 2701  [APM_RM3X8MM 2701]
H22  24438  [Keystone24438]
H23  24438  [Keystone24438]
H26  24438  [Keystone24438]
H27  24438  [Keystone24438]
H28  24438  [Keystone24438]
H29  24438  [Keystone24438]
H30  24438  [Keystone24438]
H31  24438  [Keystone24438]
H32  24438  [Keystone24438]
H33  24438  [Keystone24438]
H34  24438  [Keystone24438]
H35  24438  [Keystone24438]
H36  24438  [Keystone24438]
H37  24438  [Keystone24438]
H38  24438  [Keystone24438]
HOT_SURFACE  CAUTION HOT SURFACE  [IEC_HotSurface_medium]  (value not drawn)  (no BOM)
HOT_SURFACE1  CAUTION HOT SURFACE  [IEC_HotSurface_medium]  (value not drawn)  (no BOM)
J1  0015910100  [Molex_0015910100]
J4  S1621-46R  [Harwin_S1621-46R]
J5  S1621-46R  [Harwin_S1621-46R]
J6  S1621-46R  [Harwin_S1621-46R]
J7  S1621-46R  [Harwin_S1621-46R]
J8  S1621-46R  [Harwin_S1621-46R]
L2  value 1500 ohm  [0603]  (hidden comment: BLM18HE152SN1D)
Logo2  Pb-Free Symbol  [Pb-Free_Overlay_Small]  (no BOM)
R14  ValueDisplayed: 0  [1206]  (hidden comment: CRCW12060000Z0EA)
ZZ1  These assemblies are ESD sensitive, ESD precautions shall be observed.  [AssemblyNote]  (no BOM)
ZZ2  These assemblies must be clean and free from flux and all contaminants. Use of no clean flux is not acceptable.  [AssemblyNote]  (no BOM)
ZZ3  These assemblies must comply with workmanship standards IPC-A-610 Class 2, unless otherwise specified.  [AssemblyNote]  (no BOM)

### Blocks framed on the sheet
DC BUS CONNECTION: H22 H23 H29 H36-H38
MOTOR PHASE TERMINALS: H26-H28 H30-H35
HEAT SINK CONNECTION: H1-H8
CONTROLLER INTERFACE: J1 L2
JUMPERS: J4-J8 R14

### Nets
48V_RTN: J1.3 J1.4 J1.6 J4.1 J4.2 J5.1 J5.2 J6.1 J6.2 J7.1 J7.2 J8.1 J8.2
VDD: L2.2 R14.1 R14.2
PHU_PWM_HI: J1.7 ; off-sheet PHU_PWM_HI
PHU_PWM_LO: J1.5 ; off-sheet PHU_PWM_LO
PHV_PWM_HI: J1.1 ; off-sheet PHV_PWM_HI
PHV_PWM_LO: J1.2 ; off-sheet PHV_PWM_LO
PHW_PWM_HI: J1.8 ; off-sheet PHW_PWM_HI
PHW_PWM_LO: J1.10 ; off-sheet PHW_PWM_LO
NetJ1_9: J1.9 L2.1

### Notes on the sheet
- (near H36) DC bus positive
- (near H22) DC bus negative
- (near H35) PHASE U
- (near H31) PHASE V
- (near H26) PHASE W

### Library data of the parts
!PCB1 = PCB: Manufacturer: Any; PartNumber: TIDA-00364_PB; SymbolCreator: a0412235
FID1-FID3 = Fiducial: Fiducial mark.  There is nothing to buy or mount.; SymbolCreator: codlsc
H1-H8 = RM3X8MM 2701: MACHINE SCREW PAN PHILLIPS M3; Manufacturer: APM HEXSEAL; CompType: Standoff; SymbolCreator: a0412235
H22 H23 H26-H38 = 24438: Standoff, Hex,25mm Length, M3, Aluminum; Manufacturer: Keystone; SymbolCreator: a0412235; CompType: Hardware
HOT_SURFACE HOT_SURFACE1 = IEC_HotSurface: IEC 61010-1 Hot Surface Warning; SymbolCreator: a0412235
J1 = 0015910100: Header, 100mil, 5x2, SMT; Manufacturer: Molex; SymbolCreator: a0412235
J4-J8 = S1621-46R: JUMPER TIN SMD, SMT; Manufacturer: Harwin; SymbolCreator: a0799628; CompType: Jumper Wire; Current_A: 10
L2 = BLM18HE152SN1D: Ferrite Bead, 1500 ohm @ 100 MHz, 0.5 A, 0603; Manufacturer: MuRata; Imax_A: 0.5; Value1: 0.5 ohm; Value2: 0.5A; ZTyp@100MHz_Ohm: 1500
Logo2 = Pb-Free: SymbolCreator: a0412235
R14 = CRCW12060000Z0EA: as R95 on sheet TIDA00364_PB_GateDriver
ZZ1-ZZ3 = AssemblyNote: SymbolCreator: codlsc

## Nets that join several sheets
48V: TIDA00364_PB_PhaseU (7 pins), TIDA00364_PB_PhaseV (7 pins), TIDA00364_PB_PhaseW (7 pins)
48V_RTN: TIDA00364_PB_GateDriver (33 pins), TIDA00364_PB_PhaseU (17 pins), TIDA00364_PB_PhaseV (17 pins), TIDA00364_PB_PhaseW (17 pins), TIDA00364_PB_Hardware (13 pins)
VDD: TIDA00364_PB_GateDriver (21 pins), TIDA00364_PB_Hardware (L2.2 R14.1 R14.2)
PHASE_U: TIDA00364_PB_GateDriver (C6.2 Q6.4 U1.4), TIDA00364_PB_PhaseU (22 pins)
PHASE_V: TIDA00364_PB_GateDriver (C12.2 Q10.4 U2.4), TIDA00364_PB_PhaseV (22 pins)
PHASE_W: TIDA00364_PB_GateDriver (C18.2 Q8.4 U3.4), TIDA00364_PB_PhaseW (22 pins)
PHU_PWM_HI: TIDA00364_PB_GateDriver (R83.2), TIDA00364_PB_Hardware (J1.7)
PHU_PWM_HI_DRV: TIDA00364_PB_GateDriver (D43.1 Q6.3), TIDA00364_PB_PhaseU (5 pins)
PHU_PWM_LO: TIDA00364_PB_GateDriver (R82.2), TIDA00364_PB_Hardware (J1.5)
PHU_PWM_LO_DRV: TIDA00364_PB_GateDriver (D44.1 Q7.3), TIDA00364_PB_PhaseU (5 pins)
PHV_PWM_HI: TIDA00364_PB_GateDriver (R85.2), TIDA00364_PB_Hardware (J1.1)
PHV_PWM_HI_DRV: TIDA00364_PB_GateDriver (D47.1 Q10.3), TIDA00364_PB_PhaseV (5 pins)
PHV_PWM_LO: TIDA00364_PB_GateDriver (R84.2), TIDA00364_PB_Hardware (J1.2)
PHV_PWM_LO_DRV: TIDA00364_PB_GateDriver (D48.1 Q16.3), TIDA00364_PB_PhaseV (5 pins)
PHW_PWM_HI: TIDA00364_PB_GateDriver (R87.2), TIDA00364_PB_Hardware (J1.8)
PHW_PWM_HI_DRV: TIDA00364_PB_GateDriver (D45.1 Q8.3), TIDA00364_PB_PhaseW (5 pins)
PHW_PWM_LO: TIDA00364_PB_GateDriver (R86.2), TIDA00364_PB_Hardware (J1.10)
PHW_PWM_LO_DRV: TIDA00364_PB_GateDriver (D46.1 Q9.3), TIDA00364_PB_PhaseW (5 pins)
